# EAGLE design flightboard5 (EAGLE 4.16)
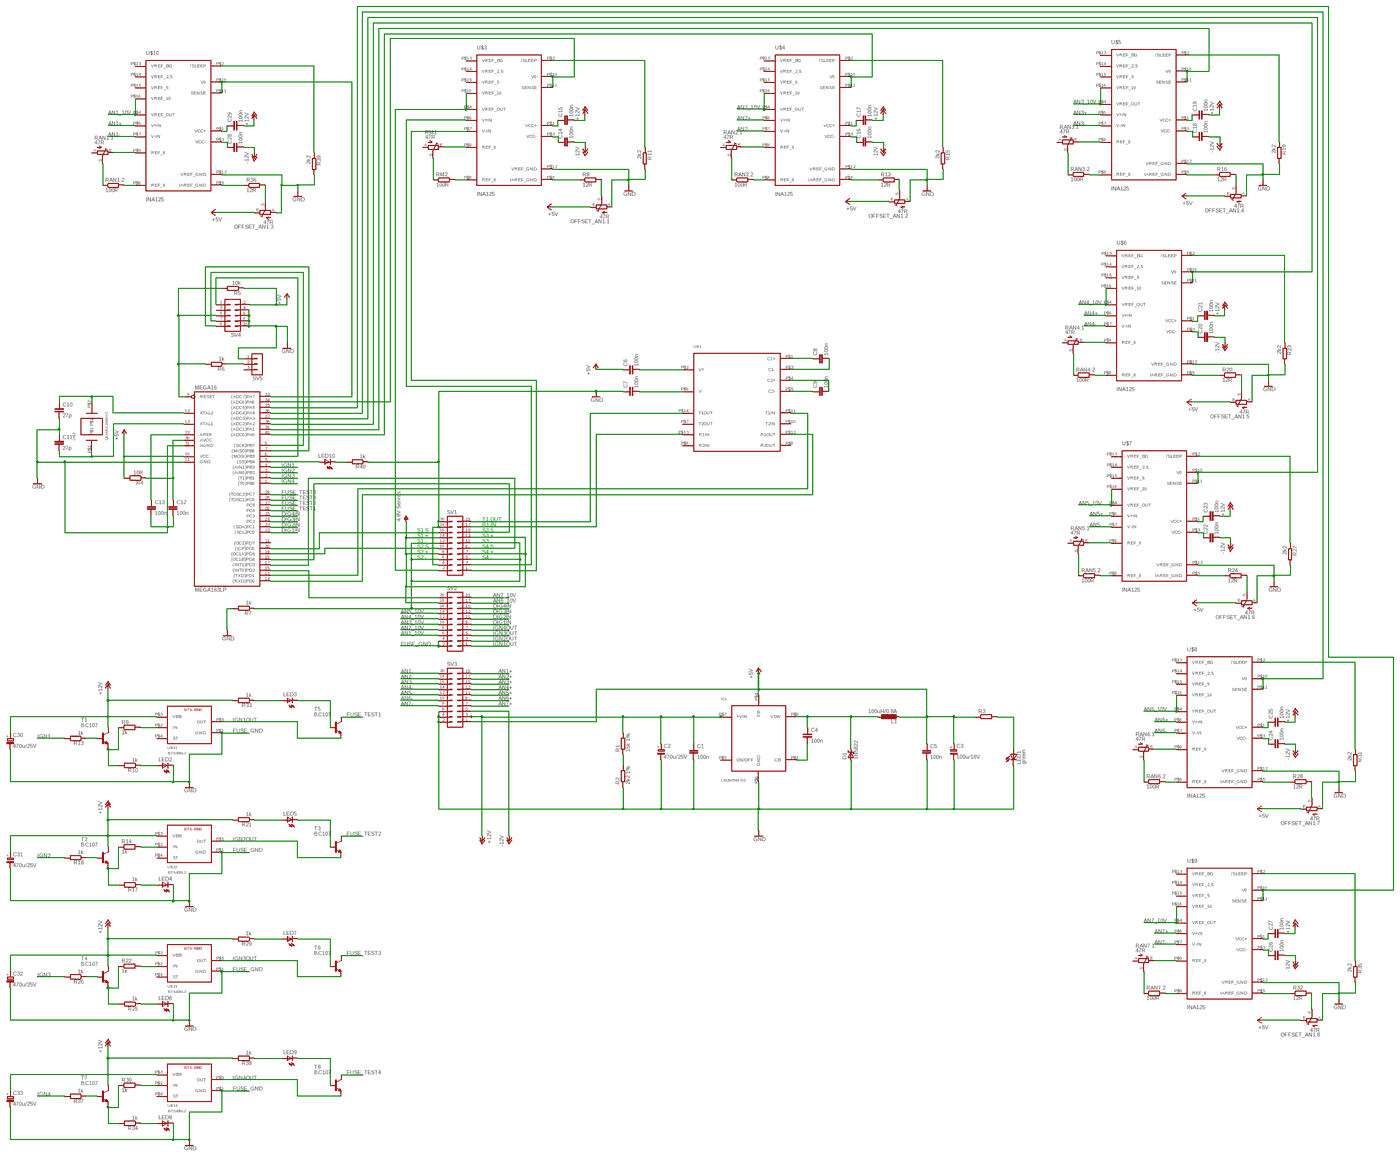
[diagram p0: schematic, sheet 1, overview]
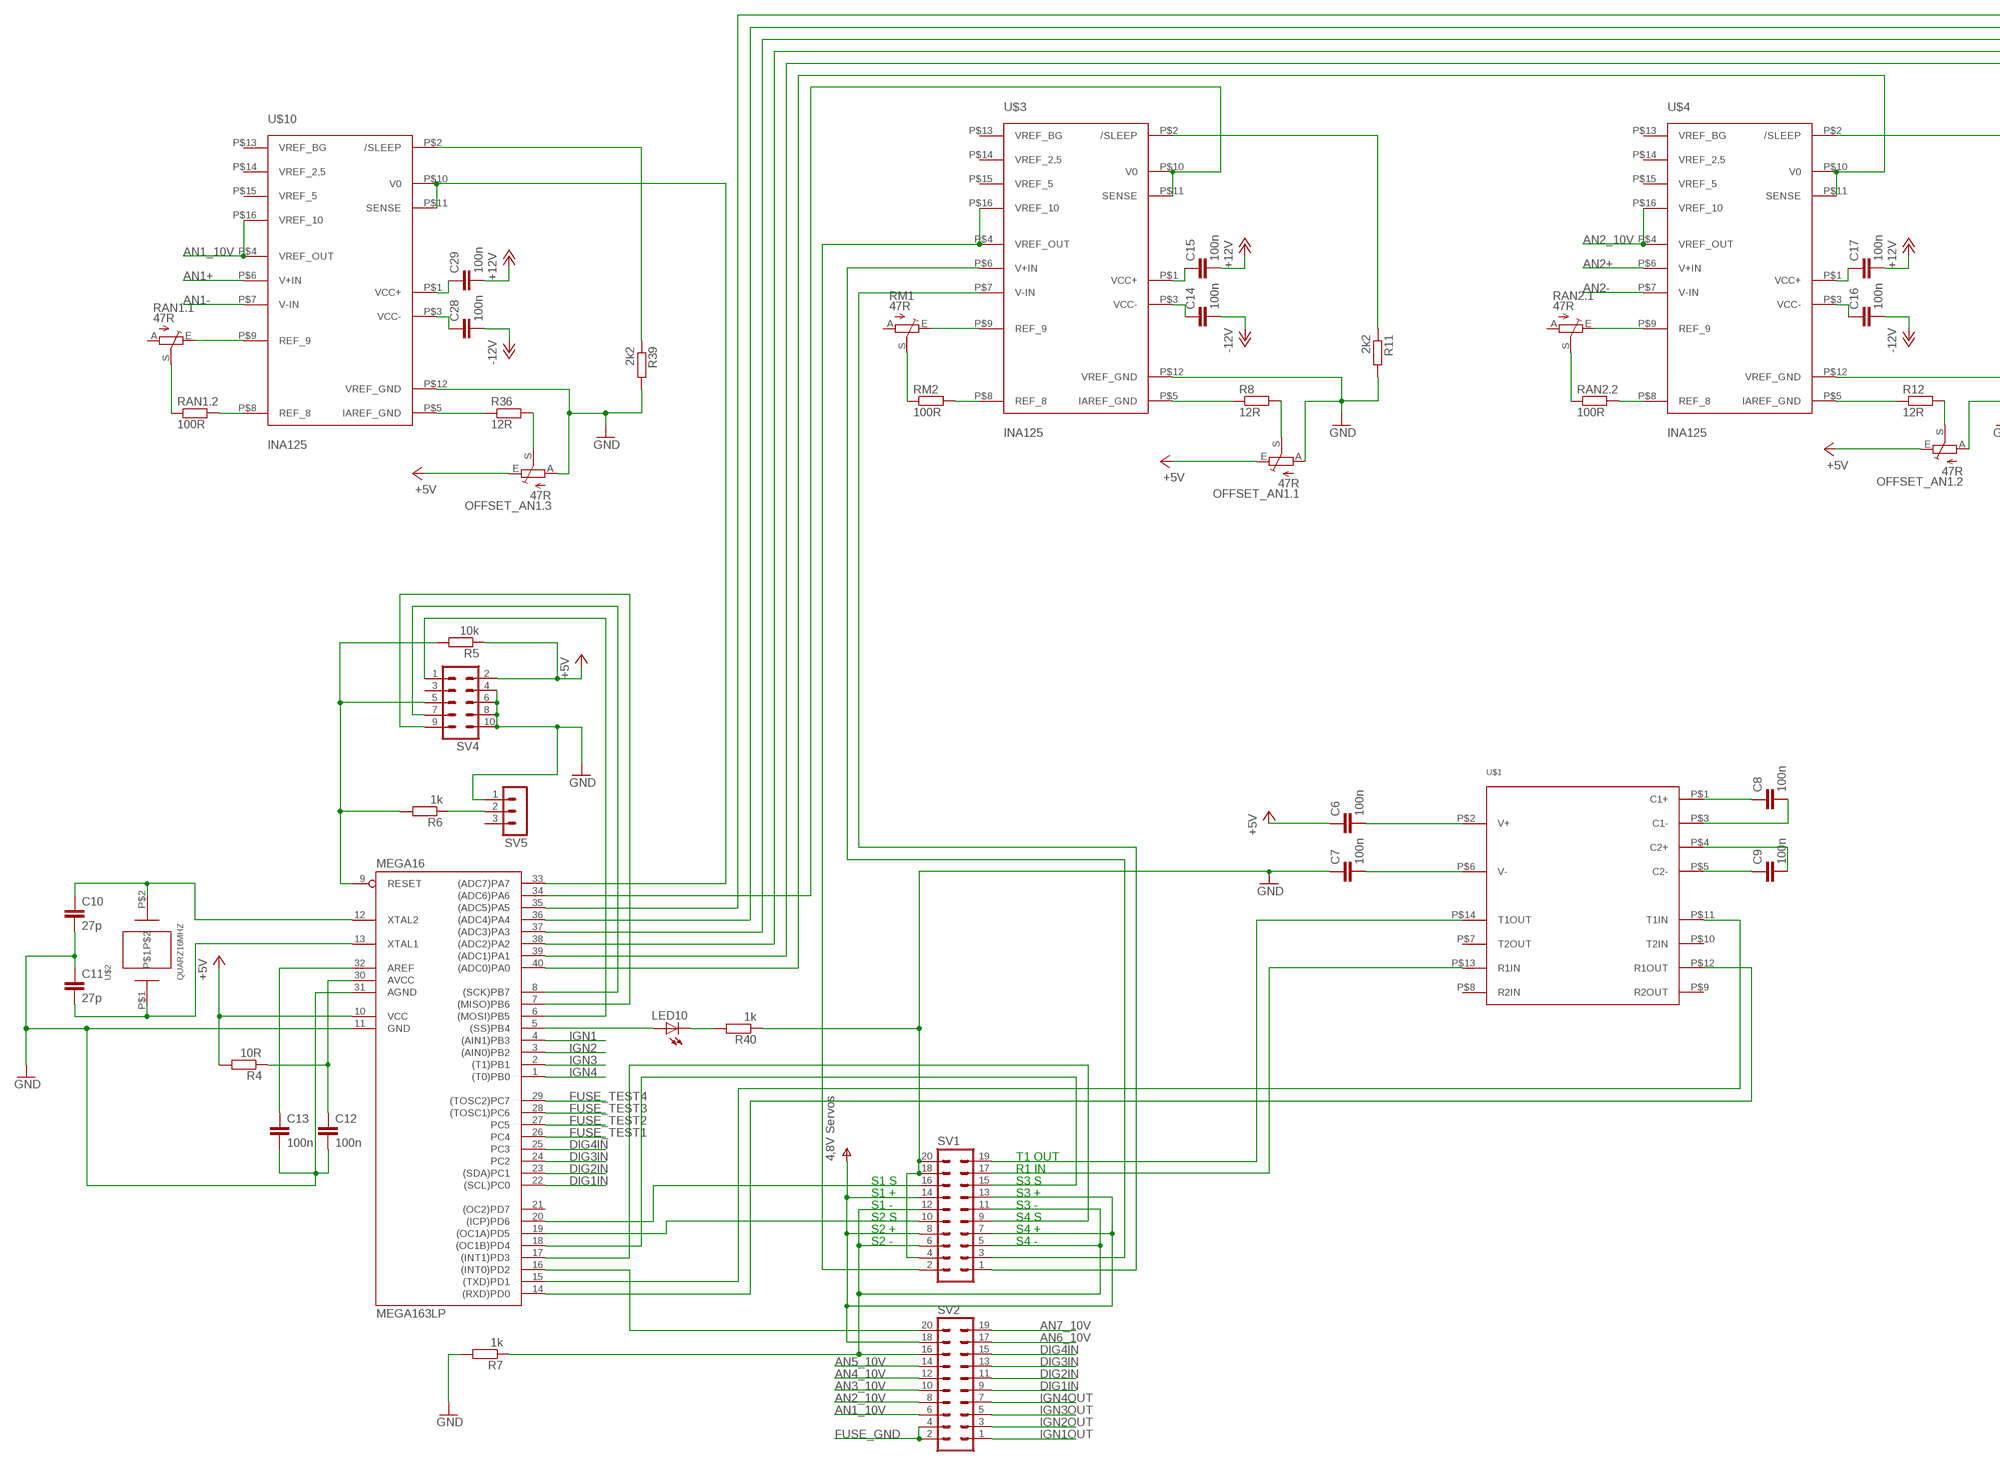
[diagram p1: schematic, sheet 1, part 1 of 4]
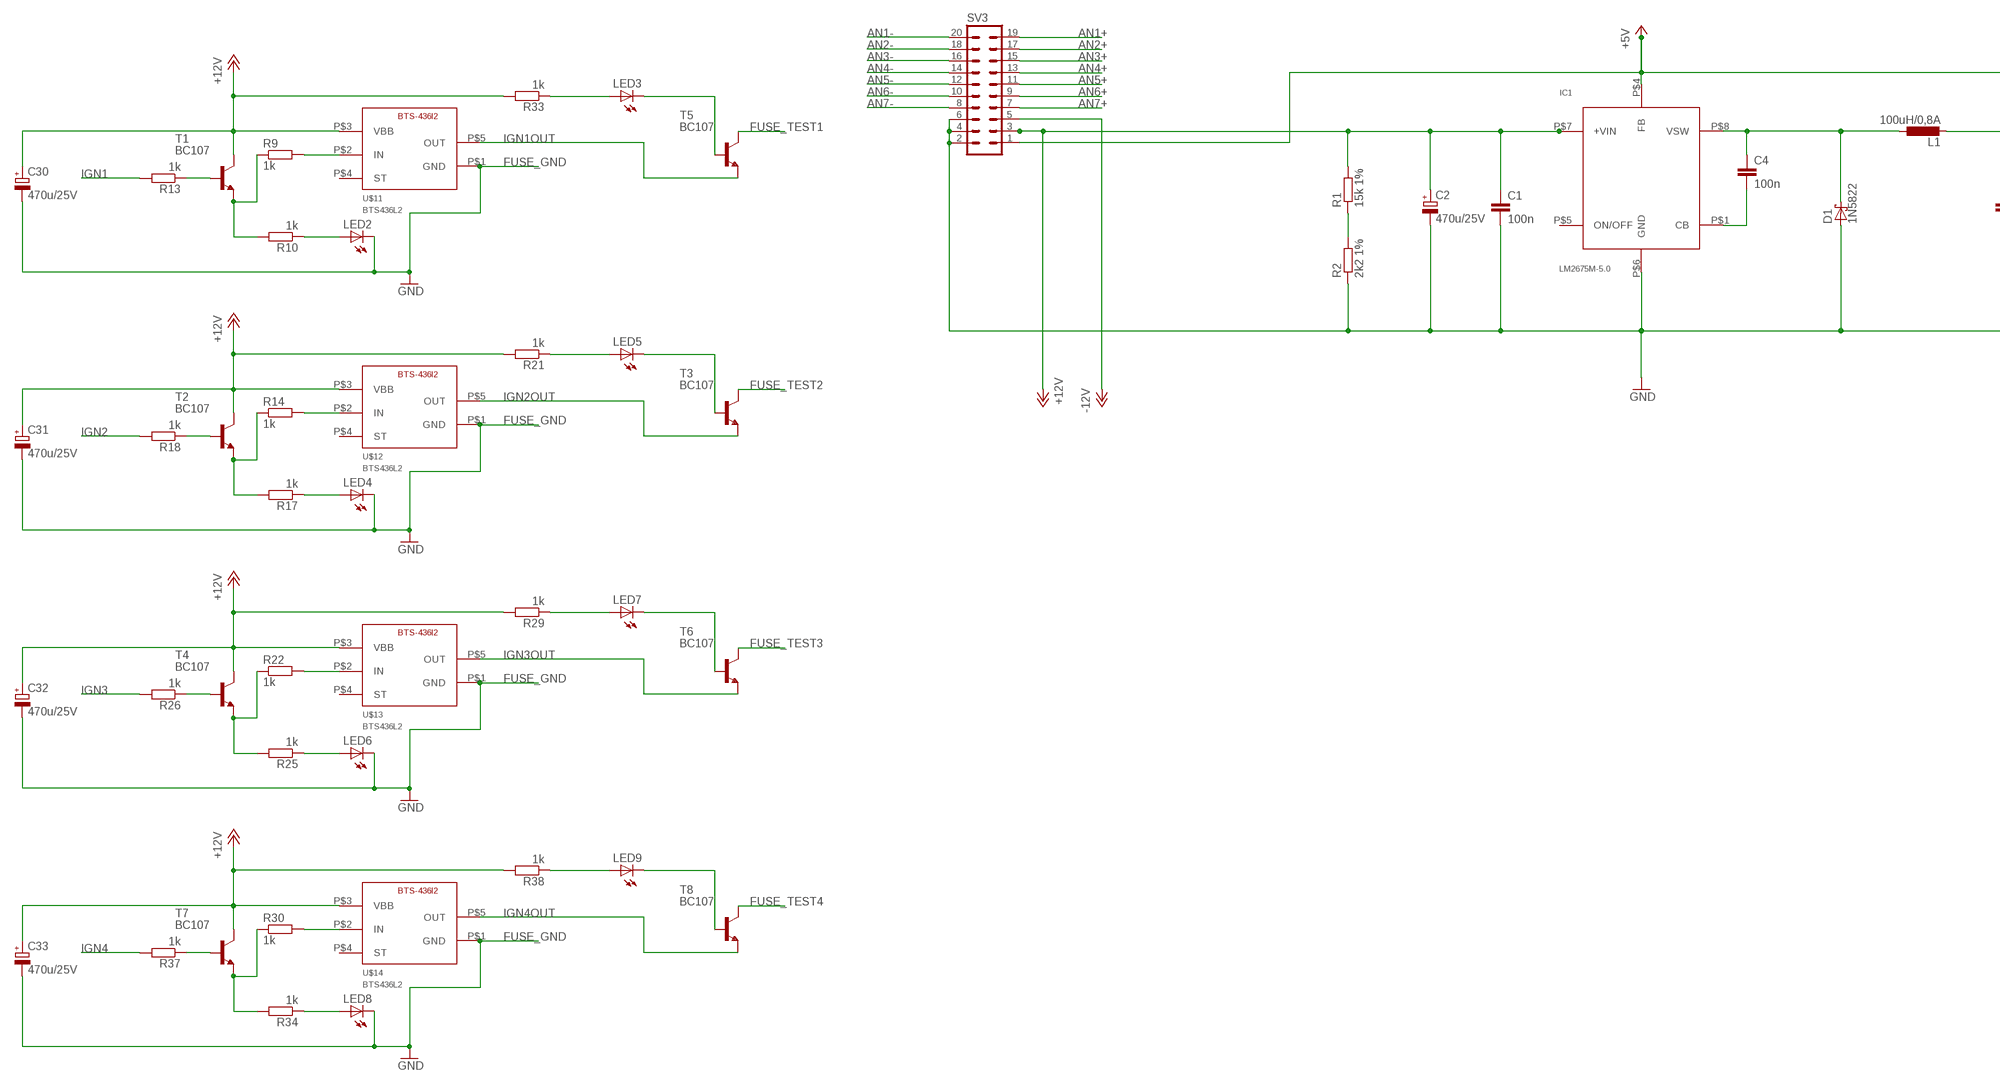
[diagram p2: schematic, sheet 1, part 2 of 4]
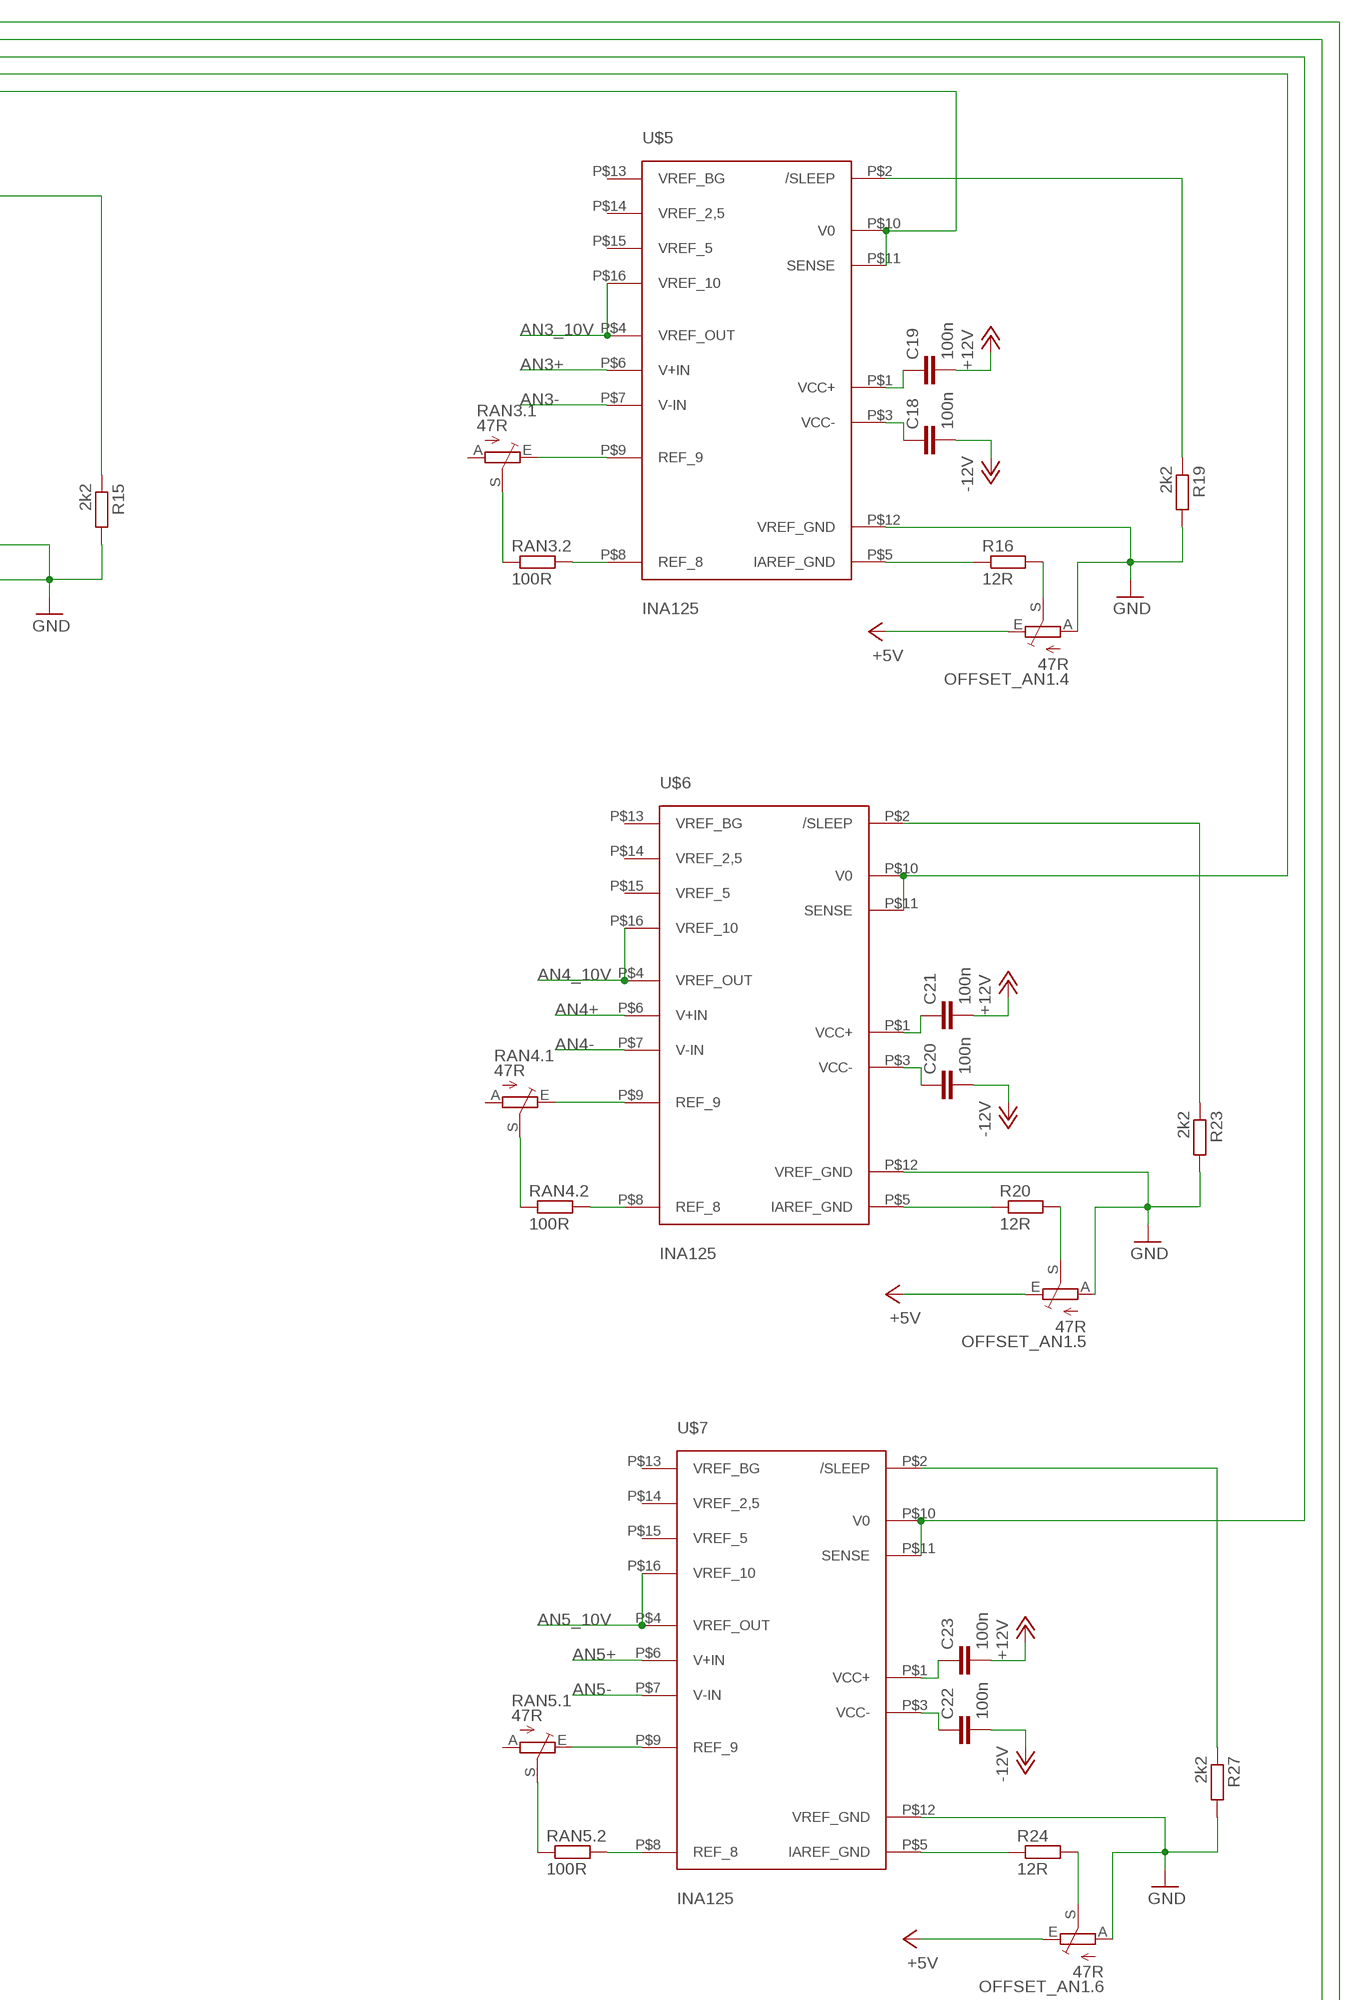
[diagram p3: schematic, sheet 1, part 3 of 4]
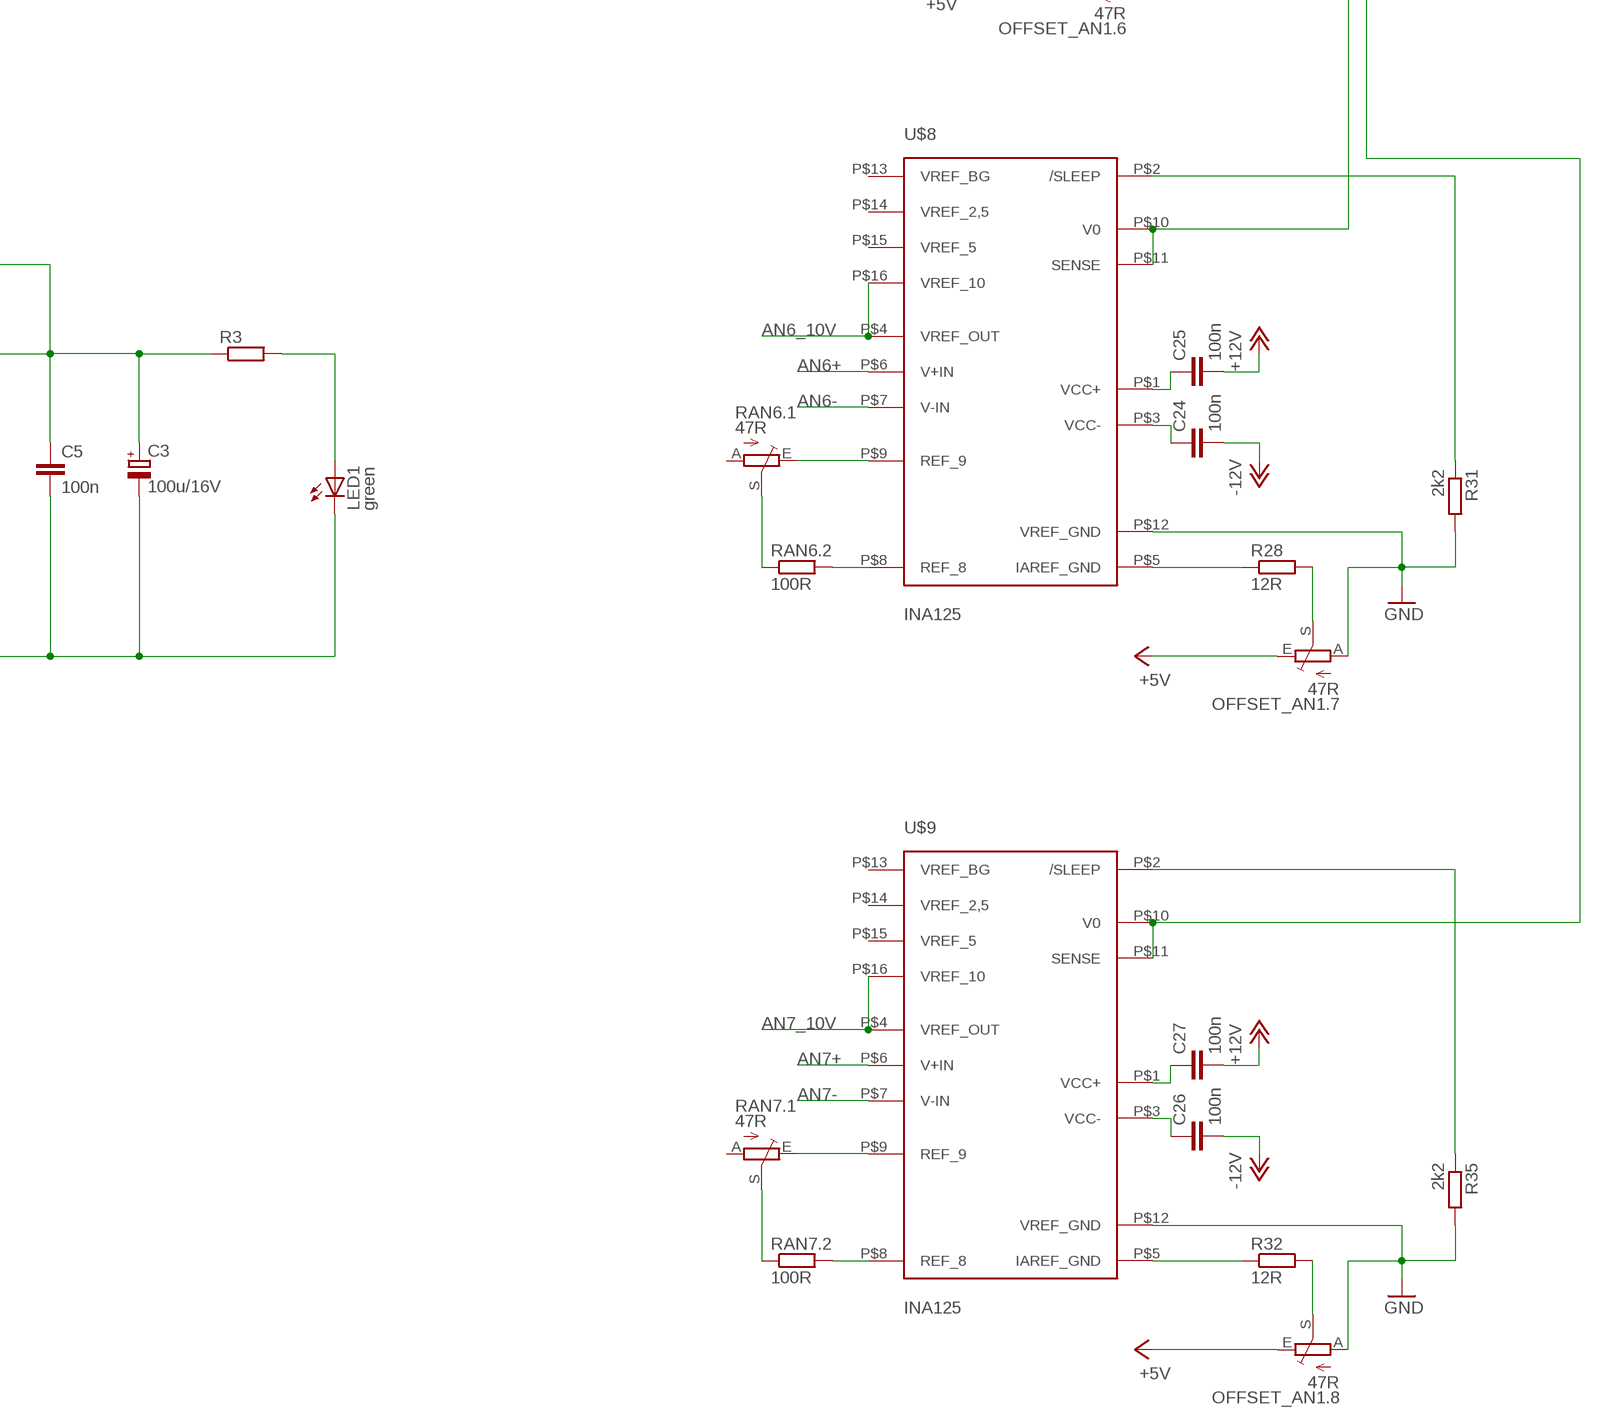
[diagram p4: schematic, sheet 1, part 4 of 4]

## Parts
C1  100n  C-EU025-024X044  [C025-024X044]
C2  470u/25V  CPOL-EUE3.5-10  [E3,5-10]
C3  100u/16V  CPOL-EUE2.5-5  [E2,5-5]
C4  100n  C-EU025-024X044  [C025-024X044]
C5  100n  C-EU025-024X044  [C025-024X044]
C6  100n  C-EU025-024X044  [C025-024X044]
C7  100n  C-EU025-024X044  [C025-024X044]
C8  100n  C-EU025-024X044  [C025-024X044]
C9  100n  C-EU025-024X044  [C025-024X044]
C10  27p  C-EU025-024X044  [C025-024X044]
C11  27p  C-EU025-024X044  [C025-024X044]
C12  100n  C-EU025-024X044  [C025-024X044]
C13  100n  C-EU025-024X044  [C025-024X044]
C14  100n  C-EU025-024X044  [C025-024X044]
C15  100n  C-EU025-024X044  [C025-024X044]
C16  100n  C-EU025-024X044  [C025-024X044]
C17  100n  C-EU025-024X044  [C025-024X044]
C18  100n  C-EU025-024X044  [C025-024X044]
C19  100n  C-EU025-024X044  [C025-024X044]
C20  100n  C-EU025-024X044  [C025-024X044]
C21  100n  C-EU025-024X044  [C025-024X044]
C22  100n  C-EU025-024X044  [C025-024X044]
C23  100n  C-EU025-024X044  [C025-024X044]
C24  100n  C-EU025-024X044  [C025-024X044]
C25  100n  C-EU025-024X044  [C025-024X044]
C26  100n  C-EU025-024X044  [C025-024X044]
C27  100n  C-EU025-024X044  [C025-024X044]
C28  100n  C-EU025-024X044  [C025-024X044]
C29  100n  C-EU025-024X044  [C025-024X044]
C30  470u/25V  CPOL-EUE3.5-10  [E3,5-10]
C31  470u/25V  CPOL-EUE3.5-10  [E3,5-10]
C32  470u/25V  CPOL-EUE3.5-10  [E3,5-10]
C33  470u/25V  CPOL-EUE3.5-10  [E3,5-10]
D1  1N5822  1N5908  [C4111-15]
IC1  LM2675M-5.0  [DIL-8]
L1  100uH/0,8A  L-EU0207/5V  [0207/5V]
LED1  green  LED3MM  [LED3MM]
LED2  LED3MM  [LED3MM]
LED3  LED3MM  [LED3MM]
LED4  LED3MM  [LED3MM]
LED5  LED3MM  [LED3MM]
LED6  LED3MM  [LED3MM]
LED7  LED3MM  [LED3MM]
LED8  LED3MM  [LED3MM]
LED9  LED3MM  [LED3MM]
LED10  LED3MM  [LED3MM]
MEGA16  MEGA163LP  [DIL40]
OFFSET_AN1.1  47R  TRIM_EU-B90P  [SP19L]
OFFSET_AN1.2  47R  TRIM_EU-B90P  [SP19L]
OFFSET_AN1.3  47R  TRIM_EU-B90P  [SP19L]
OFFSET_AN1.4  47R  TRIM_EU-B90P  [SP19L]
OFFSET_AN1.5  47R  TRIM_EU-B90P  [SP19L]
OFFSET_AN1.6  47R  TRIM_EU-B90P  [SP19L]
OFFSET_AN1.7  47R  TRIM_EU-B90P  [SP19L]
OFFSET_AN1.8  47R  TRIM_EU-B90P  [SP19L]
R1  15k 1%  R-EU_0207/10  [0207/10]
R2  2k2 1%  R-EU_0207/10  [0207/10]
R3  R-EU_0207/10  [0207/10]
R4  10R  R-EU_0309/10  [0309/10]
R5  10k  R-EU_0207/10  [0207/10]
R6  1k  R-EU_0207/10  [0207/10]
R7  1k  R-EU_0207/10  [0207/10]
R8  12R  R-EU_0309/10  [0309/10]
R9  1k  R-EU_0207/10  [0207/10]
R10  1k  R-EU_0207/10  [0207/10]
R11  2k2  R-EU_0309/10  [0309/10]
R12  12R  R-EU_0309/10  [0309/10]
R13  1k  R-EU_0207/10  [0207/10]
R14  1k  R-EU_0207/10  [0207/10]
R15  2k2  R-EU_0309/10  [0309/10]
R16  12R  R-EU_0309/10  [0309/10]
R17  1k  R-EU_0207/10  [0207/10]
R18  1k  R-EU_0207/10  [0207/10]
R19  2k2  R-EU_0309/10  [0309/10]
R20  12R  R-EU_0309/10  [0309/10]
R21  1k  R-EU_0207/10  [0207/10]
R22  1k  R-EU_0207/10  [0207/10]
R23  2k2  R-EU_0309/10  [0309/10]
R24  12R  R-EU_0309/10  [0309/10]
R25  1k  R-EU_0207/10  [0207/10]
R26  1k  R-EU_0207/10  [0207/10]
R27  2k2  R-EU_0309/10  [0309/10]
R28  12R  R-EU_0309/10  [0309/10]
R29  1k  R-EU_0207/10  [0207/10]
R30  1k  R-EU_0207/10  [0207/10]
R31  2k2  R-EU_0309/10  [0309/10]
R32  12R  R-EU_0309/10  [0309/10]
R33  1k  R-EU_0207/10  [0207/10]
R34  1k  R-EU_0207/10  [0207/10]
R35  2k2  R-EU_0309/10  [0309/10]
R36  12R  R-EU_0309/10  [0309/10]
R37  1k  R-EU_0207/10  [0207/10]
R38  1k  R-EU_0207/10  [0207/10]
R39  2k2  R-EU_0309/10  [0309/10]
R40  1k  R-EU_0309/10  [0309/10]
RAN1.1  47R  TRIM_EU-B90P  [SP19L]
RAN1.2  100R  R-EU_0309/10  [0309/10]
RAN2.1  47R  TRIM_EU-B90P  [SP19L]
RAN2.2  100R  R-EU_0309/10  [0309/10]
RAN3.1  47R  TRIM_EU-B90P  [SP19L]
RAN3.2  100R  R-EU_0309/10  [0309/10]
RAN4.1  47R  TRIM_EU-B90P  [SP19L]
RAN4.2  100R  R-EU_0309/10  [0309/10]
RAN5.1  47R  TRIM_EU-B90P  [SP19L]
RAN5.2  100R  R-EU_0309/10  [0309/10]
RAN6.1  47R  TRIM_EU-B90P  [SP19L]
RAN6.2  100R  R-EU_0309/10  [0309/10]
RAN7.1  47R  TRIM_EU-B90P  [SP19L]
RAN7.2  100R  R-EU_0309/10  [0309/10]
RM1  47R  TRIM_EU-B90P  [SP19L]
RM2  100R  R-EU_0309/10  [0309/10]
SV1  MA10-2W  [MA10-2W]
SV2  MA10-2W  [MA10-2W]
SV3  MA10-2W  [MA10-2W]
SV4  MA05-2  [MA05-2]
SV5  MA03-1  [MA03-1]
T1  BC107  [TO18]
T2  BC107  [TO18]
T3  BC107  [TO18]
T4  BC107  [TO18]
T5  BC107  [TO18]
T6  BC107  [TO18]
T7  BC107  [TO18]
T8  BC107  [TO18]
U$1  MAX232  [DIL-16]
U$2  QUARZ16MHZ  [QUARZ16MHZ]
U$3  INA125  [DIL-16]
U$4  INA125  [DIL-16]
U$5  INA125  [DIL-16]
U$6  INA125  [DIL-16]
U$7  INA125  [DIL-16]
U$8  INA125  [DIL-16]
U$9  INA125  [DIL-16]
U$10  INA125  [DIL-16]
U$11  BTS436L2  [TO-GEHÄUSE]
U$12  BTS436L2  [TO-GEHÄUSE]
U$13  BTS436L2  [TO-GEHÄUSE]
U$14  BTS436L2  [TO-GEHÄUSE]

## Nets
+5V: C3.+ C5.1 C6.1 IC1.P$4(FB) L1.2 MEGA16.10(VCC) OFFSET_AN1.1.E OFFSET_AN1.2.E OFFSET_AN1.3.E OFFSET_AN1.4.E OFFSET_AN1.5.E OFFSET_AN1.6.E OFFSET_AN1.7.E OFFSET_AN1.8.E R3.1 R4.2 R5.1 SV3.1 SV4.2
+12V: C1.1 C2.+ C15.2 C17.2 C19.2 C21.2 C23.2 C25.2 C27.2 C29.2 C30.+ C31.+ C32.+ C33.+ IC1.P$7(+VIN) R1.2 R21.2 R29.2 R33.2 R38.2 SV3.3 T1.3(C) T2.3(C) T4.3(C) T7.3(C) U$11.P$3(VBB) U$12.P$3(VBB) U$13.P$3(VBB) U$14.P$3(VBB)
-12V: C14.2 C16.2 C18.2 C20.2 C22.2 C24.2 C26.2 C28.2 SV3.5
AN1+: SV3.19 U$10.P$6(V+IN)
AN1-: SV3.20 U$10.P$7(V-IN)
AN1_10V: SV2.6 U$10.P$4(VREF_OUT) U$10.P$16(VREF_10)
AN2+: SV3.17 U$4.P$6(V+IN)
AN2-: SV3.18 U$4.P$7(V-IN)
AN2_10V: SV2.8 U$4.P$4(VREF_OUT) U$4.P$16(VREF_10)
AN3+: SV3.15 U$5.P$6(V+IN)
AN3-: SV3.16 U$5.P$7(V-IN)
AN3_10V: SV2.10 U$5.P$4(VREF_OUT) U$5.P$16(VREF_10)
AN4+: SV3.13 U$6.P$6(V+IN)
AN4-: SV3.14 U$6.P$7(V-IN)
AN4_10V: SV2.12 U$6.P$4(VREF_OUT) U$6.P$16(VREF_10)
AN5+: SV3.11 U$7.P$6(V+IN)
AN5-: SV3.12 U$7.P$7(V-IN)
AN5_10V: SV2.14 U$7.P$4(VREF_OUT) U$7.P$16(VREF_10)
AN6+: SV3.9 U$8.P$6(V+IN)
AN6-: SV3.10 U$8.P$7(V-IN)
AN6_10V: SV2.17 U$8.P$4(VREF_OUT) U$8.P$16(VREF_10)
AN7+: SV3.7 U$9.P$6(V+IN)
AN7-: SV3.8 U$9.P$7(V-IN)
AN7_10V: SV2.19 U$9.P$4(VREF_OUT) U$9.P$16(VREF_10)
DIG1IN: MEGA16.22((SCL)PC0) SV2.9
DIG2IN: MEGA16.23((SDA)PC1) SV2.11
DIG3IN: MEGA16.24(PC2) SV2.13
DIG4IN: MEGA16.25(PC3) SV2.15
FUSE_GND: C1.2 C2.- C3.- C5.2 C7.1 C10.2 C11.1 C12.2 C13.2 C30.- C31.- C32.- C33.- D1.A IC1.P$6(GND) LED1.K(C) LED2.K(C) LED4.K(C) LED6.K(C) LED8.K(C) MEGA16.11(GND) MEGA16.31(AGND) OFFSET_AN1.1.A OFFSET_AN1.2.A OFFSET_AN1.3.A OFFSET_AN1.4.A OFFSET_AN1.5.A OFFSET_AN1.6.A OFFSET_AN1.7.A OFFSET_AN1.8.A R2.1 R7.2 R11.2 R15.2 R19.2 R23.2 R27.2 R31.2 R35.2 R39.2 R40.1 SV1.4 SV1.18 SV1.20 SV2.2 SV2.4 SV3.2 SV3.4 SV3.6 SV4.4 SV4.6 SV4.8 SV4.10 SV5.1 U$3.P$12(VREF_GND) U$4.P$12(VREF_GND) U$5.P$12(VREF_GND) U$6.P$12(VREF_GND) U$7.P$12(VREF_GND) U$8.P$12(VREF_GND) U$9.P$12(VREF_GND) U$10.P$12(VREF_GND) U$11.P$1(GND) U$12.P$1(GND) U$13.P$1(GND) U$14.P$1(GND) ; supply symbol labelled GND
FUSE_TEST1: MEGA16.26(PC4) T5.3(C)
FUSE_TEST2: MEGA16.27(PC5) T3.3(C)
FUSE_TEST3: MEGA16.28((TOSC1)PC6) T6.3(C)
FUSE_TEST4: MEGA16.29((TOSC2)PC7) T8.3(C)
IGN1: MEGA16.4((AIN1)PB3) R13.2
IGN1OUT: SV2.1 T5.1(E) U$11.P$5(OUT)
IGN2: MEGA16.3((AIN0)PB2) R18.2
IGN2OUT: SV2.3 T3.1(E) U$12.P$5(OUT)
IGN3: MEGA16.2((T1)PB1) R26.2
IGN3OUT: SV2.5 T6.1(E) U$13.P$5(OUT)
IGN4: MEGA16.1((T0)PB0) R37.2
IGN4OUT: SV2.7 T8.1(E) U$14.P$5(OUT)
N$1: R1.1 R2.2
N$2: C4.2 IC1.P$1(CB)
N$3: C4.1 D1.C IC1.P$8(VSW) L1.1
N$4: C6.2 U$1.P$2(V+)
N$5: LED1.A R3.2
N$6: C7.2 U$1.P$6(V-)
N$7: C9.1 U$1.P$5(C2-)
N$8: C8.1 U$1.P$1(C1+)
N$9: C8.2 U$1.P$3(C1-)
N$10: C9.2 U$1.P$4(C2+)
N$11: SV1.17 U$1.P$13(R1IN)
N$12: SV1.19 U$1.P$14(T1OUT)
N$13: MEGA16.14((RXD)PD0) U$1.P$12(R1OUT)
N$14: MEGA16.15((TXD)PD1) U$1.P$11(T1IN)
N$15: C11.2 MEGA16.13(XTAL1) U$2.P$1
N$16: C10.1 MEGA16.12(XTAL2) U$2.P$2
N$17: MEGA16.17((INT1)PD3) SV1.9
N$18: C12.1 MEGA16.30(AVCC) R4.1
N$19: C13.1 MEGA16.32(AREF)
N$20: MEGA16.9(RESET) R5.2 R6.2 SV4.5
N$21: MEGA16.16((INT0)PD2) SV2.20
N$22: R6.1 SV5.2
N$23: MEGA16.20((ICP)PD6) SV1.16
N$24: MEGA16.19((OC1A)PD5) SV1.10
N$25: R7.1 SV1.5 SV1.6 SV1.11 SV1.12 SV2.16
N$26: MEGA16.18((OC1B)PD4) SV1.15
N$27: C14.1 U$3.P$3(VCC-)
N$28: C15.1 U$3.P$1(VCC+)
N$29: MEGA16.34((ADC6)PA6) U$3.P$10(V0) U$3.P$11(SENSE)
N$30: RM2.2 U$3.P$8(REF_8)
N$31: RM1.E U$3.P$9(REF_9)
N$32: RM1.S RM2.1
N$33: SV1.2 U$3.P$4(VREF_OUT) U$3.P$16(VREF_10)
N$34: R11.1 U$3.P$2(/SLEEP)
N$35: C16.1 U$4.P$3(VCC-)
N$36: SV1.3 U$3.P$6(V+IN)
N$37: SV1.1 U$3.P$7(V-IN)
N$38: C17.1 U$4.P$1(VCC+)
N$39: MEGA16.40((ADC0)PA0) U$4.P$10(V0) U$4.P$11(SENSE)
N$40: RAN2.2.2 U$4.P$8(REF_8)
N$41: RAN2.1.E U$4.P$9(REF_9)
N$42: RAN2.1.S RAN2.2.1
N$43: R15.1 U$4.P$2(/SLEEP)
N$44: OFFSET_AN1.3.S R36.2
N$45: R9.2 U$11.P$2(IN)
N$46: OFFSET_AN1.1.S R8.2
N$47: C18.1 U$5.P$3(VCC-)
N$48: C19.1 U$5.P$1(VCC+)
N$49: C26.1 U$9.P$3(VCC-)
N$50: RAN3.2.2 U$5.P$8(REF_8)
N$51: RAN3.1.E U$5.P$9(REF_9)
N$52: RAN3.1.S RAN3.2.1
N$53: R19.1 U$5.P$2(/SLEEP)
N$54: OFFSET_AN1.2.S R12.2
N$55: OFFSET_AN1.4.S R16.2
N$56: OFFSET_AN1.5.S R20.2
N$57: C20.1 U$6.P$3(VCC-)
N$58: C21.1 U$6.P$1(VCC+)
N$59: C27.1 U$9.P$1(VCC+)
N$60: RAN4.2.2 U$6.P$8(REF_8)
N$61: RAN4.1.E U$6.P$9(REF_9)
N$62: RAN4.1.S RAN4.2.1
N$63: R23.1 U$6.P$2(/SLEEP)
N$64: OFFSET_AN1.6.S R24.2
N$65: OFFSET_AN1.7.S R28.2
N$66: R14.2 U$12.P$2(IN)
N$67: C22.1 U$7.P$3(VCC-)
N$68: C23.1 U$7.P$1(VCC+)
N$69: C28.1 U$10.P$3(VCC-)
N$70: RAN5.2.2 U$7.P$8(REF_8)
N$71: RAN5.1.E U$7.P$9(REF_9)
N$72: RAN5.1.S RAN5.2.1
N$73: R27.1 U$7.P$2(/SLEEP)
N$74: R9.1 R10.2 T1.1(E)
N$75: R13.1 T1.2(B)
N$76: LED3.K(C) T5.2(B)
N$77: C24.1 U$8.P$3(VCC-)
N$78: C25.1 U$8.P$1(VCC+)
N$79: C29.1 U$10.P$1(VCC+)
N$80: RAN6.2.2 U$8.P$8(REF_8)
N$81: RAN6.1.E U$8.P$9(REF_9)
N$82: RAN6.1.S RAN6.2.1
N$83: R31.1 U$8.P$2(/SLEEP)
N$84: R14.1 R17.2 T2.1(E)
N$85: R18.1 T2.2(B)
N$86: LED4.A R17.1
N$87: RAN7.2.2 U$9.P$8(REF_8)
N$88: MEGA16.39((ADC1)PA1) U$5.P$10(V0) U$5.P$11(SENSE)
N$89: MEGA16.38((ADC2)PA2) U$6.P$10(V0) U$6.P$11(SENSE)
N$90: MEGA16.37((ADC3)PA3) U$7.P$10(V0) U$7.P$11(SENSE)
N$91: MEGA16.36((ADC4)PA4) U$8.P$10(V0) U$8.P$11(SENSE)
N$92: MEGA16.35((ADC5)PA5) U$9.P$10(V0) U$9.P$11(SENSE)
N$93: RAN7.1.E U$9.P$9(REF_9)
N$94: RAN7.1.S RAN7.2.1
N$95: R35.1 U$9.P$2(/SLEEP)
N$96: LED5.A R21.1
N$97: LED5.K(C) T3.2(B)
N$98: R22.2 U$13.P$2(IN)
N$99: MEGA16.33((ADC7)PA7) U$10.P$10(V0) U$10.P$11(SENSE)
N$100: RAN1.2.2 U$10.P$8(REF_8)
N$101: RAN1.1.E U$10.P$9(REF_9)
N$102: RAN1.1.S RAN1.2.1
N$103: R39.1 U$10.P$2(/SLEEP)
N$104: R22.1 R25.2 T4.1(E)
N$105: R26.1 T4.2(B)
N$106: LED6.A R25.1
N$107: MEGA16.8((SCK)PB7) SV4.7
N$108: MEGA16.6((MOSI)PB5) SV4.1
N$109: MEGA16.7((MISO)PB6) SV4.9
N$110: LED7.A R29.1
N$111: LED7.K(C) T6.2(B)
N$112: R36.1 U$10.P$5(IAREF_GND)
N$113: R8.1 U$3.P$5(IAREF_GND)
N$114: R12.1 U$4.P$5(IAREF_GND)
N$115: R16.1 U$5.P$5(IAREF_GND)
N$116: R20.1 U$6.P$5(IAREF_GND)
N$117: R24.1 U$7.P$5(IAREF_GND)
N$118: R28.1 U$8.P$5(IAREF_GND)
N$119: R32.1 U$9.P$5(IAREF_GND)
N$120: LED2.A R10.1
N$121: LED3.A R33.1
N$122: R30.2 U$14.P$2(IN)
N$123: R30.1 R34.2 T7.1(E)
N$124: R37.1 T7.2(B)
N$125: LED8.A R34.1
N$126: LED9.A R38.1
N$127: LED9.K(C) T8.2(B)
N$128: LED10.A MEGA16.5((SS)PB4)
N$129: LED10.K(C) R40.2
N$130: OFFSET_AN1.8.S R32.2
V+: SV1.7 SV1.8 SV1.13 SV1.14 SV2.18 ; supply symbol labelled 4,8V Servos
Unconnected: IC1.P$5(ON/OFF) MEGA16.21((OC2)PD7) RAN1.1.A RAN2.1.A RAN3.1.A RAN4.1.A RAN5.1.A RAN6.1.A RAN7.1.A RM1.A SV4.3 SV5.3 U$1.P$7(T2OUT) U$1.P$8(R2IN) U$1.P$9(R2OUT) U$1.P$10(T2IN) U$3.P$13(VREF_BG) U$3.P$14(VREF_2,5) U$3.P$15(VREF_5) U$4.P$13(VREF_BG) U$4.P$14(VREF_2,5) U$4.P$15(VREF_5) U$5.P$13(VREF_BG) U$5.P$14(VREF_2,5) U$5.P$15(VREF_5) U$6.P$13(VREF_BG) U$6.P$14(VREF_2,5) U$6.P$15(VREF_5) U$7.P$13(VREF_BG) U$7.P$14(VREF_2,5) U$7.P$15(VREF_5) U$8.P$13(VREF_BG) U$8.P$14(VREF_2,5) U$8.P$15(VREF_5) U$9.P$13(VREF_BG) U$9.P$14(VREF_2,5) U$9.P$15(VREF_5) U$10.P$13(VREF_BG) U$10.P$14(VREF_2,5) U$10.P$15(VREF_5) U$11.P$4(ST) U$12.P$4(ST) U$13.P$4(ST) U$14.P$4(ST)

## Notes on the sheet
- T1 OUT
- R1 IN
- S1 S | S3 S
- S1 + | S3 +
- S1 - | S3 -
- S2 S | S4 S
- S2 + | S4 +
- S2 - | S4 -

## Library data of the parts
C1 C4-C29 = rcl:C-EU: CAPACITOR, European symbol
C2 C3 C30-C33 = rcl:CPOL-EU: POLARIZED CAPACITOR, European symbol
D1 = diode:1N5908: DIODE
IC1 = eigene:LM2675M-5.0
L1 = rcl:L-EU: INDUCTOR, European symbol
LED1-LED10 = led:LED: LED
MEGA16 = atmel:MEGA163*P: MICROCONTROLLER 16 Kbytes FLASH, 1 Kbytes EEPROM 1 Kbytes SRAM UART 8-channel 10 bit ADC hardware multiplier
OFFSET_AN1.1-OFFSET_AN1.8 RAN1.1 RAN2.1 RAN3.1 RAN4.1 RAN5.1 RAN6.1 RAN7.1 RM1 = pot:TRIM_EU-: POTENTIOMETER
R1-R40 RAN1.2 RAN2.2 RAN3.2 RAN4.2 RAN5.2 RAN6.2 RAN7.2 RM2 = rcl:R-EU_: RESISTOR, European symbol
SV1-SV3 = con-lstb:MA10-2W: PIN HEADER
SV4 = con-lstb:MA05-2: PIN HEADER
SV5 = con-lstb:MA03-1: PIN HEADER
T1-T8 = transistor:BC107: NPN TRANSISTOR
U$1 = eigene:MAX232
U$2 = eigene:QUARZ16MHZ
U$3-U$10 = eigene:INA125
U$11-U$14 = eigene:BTS436L2

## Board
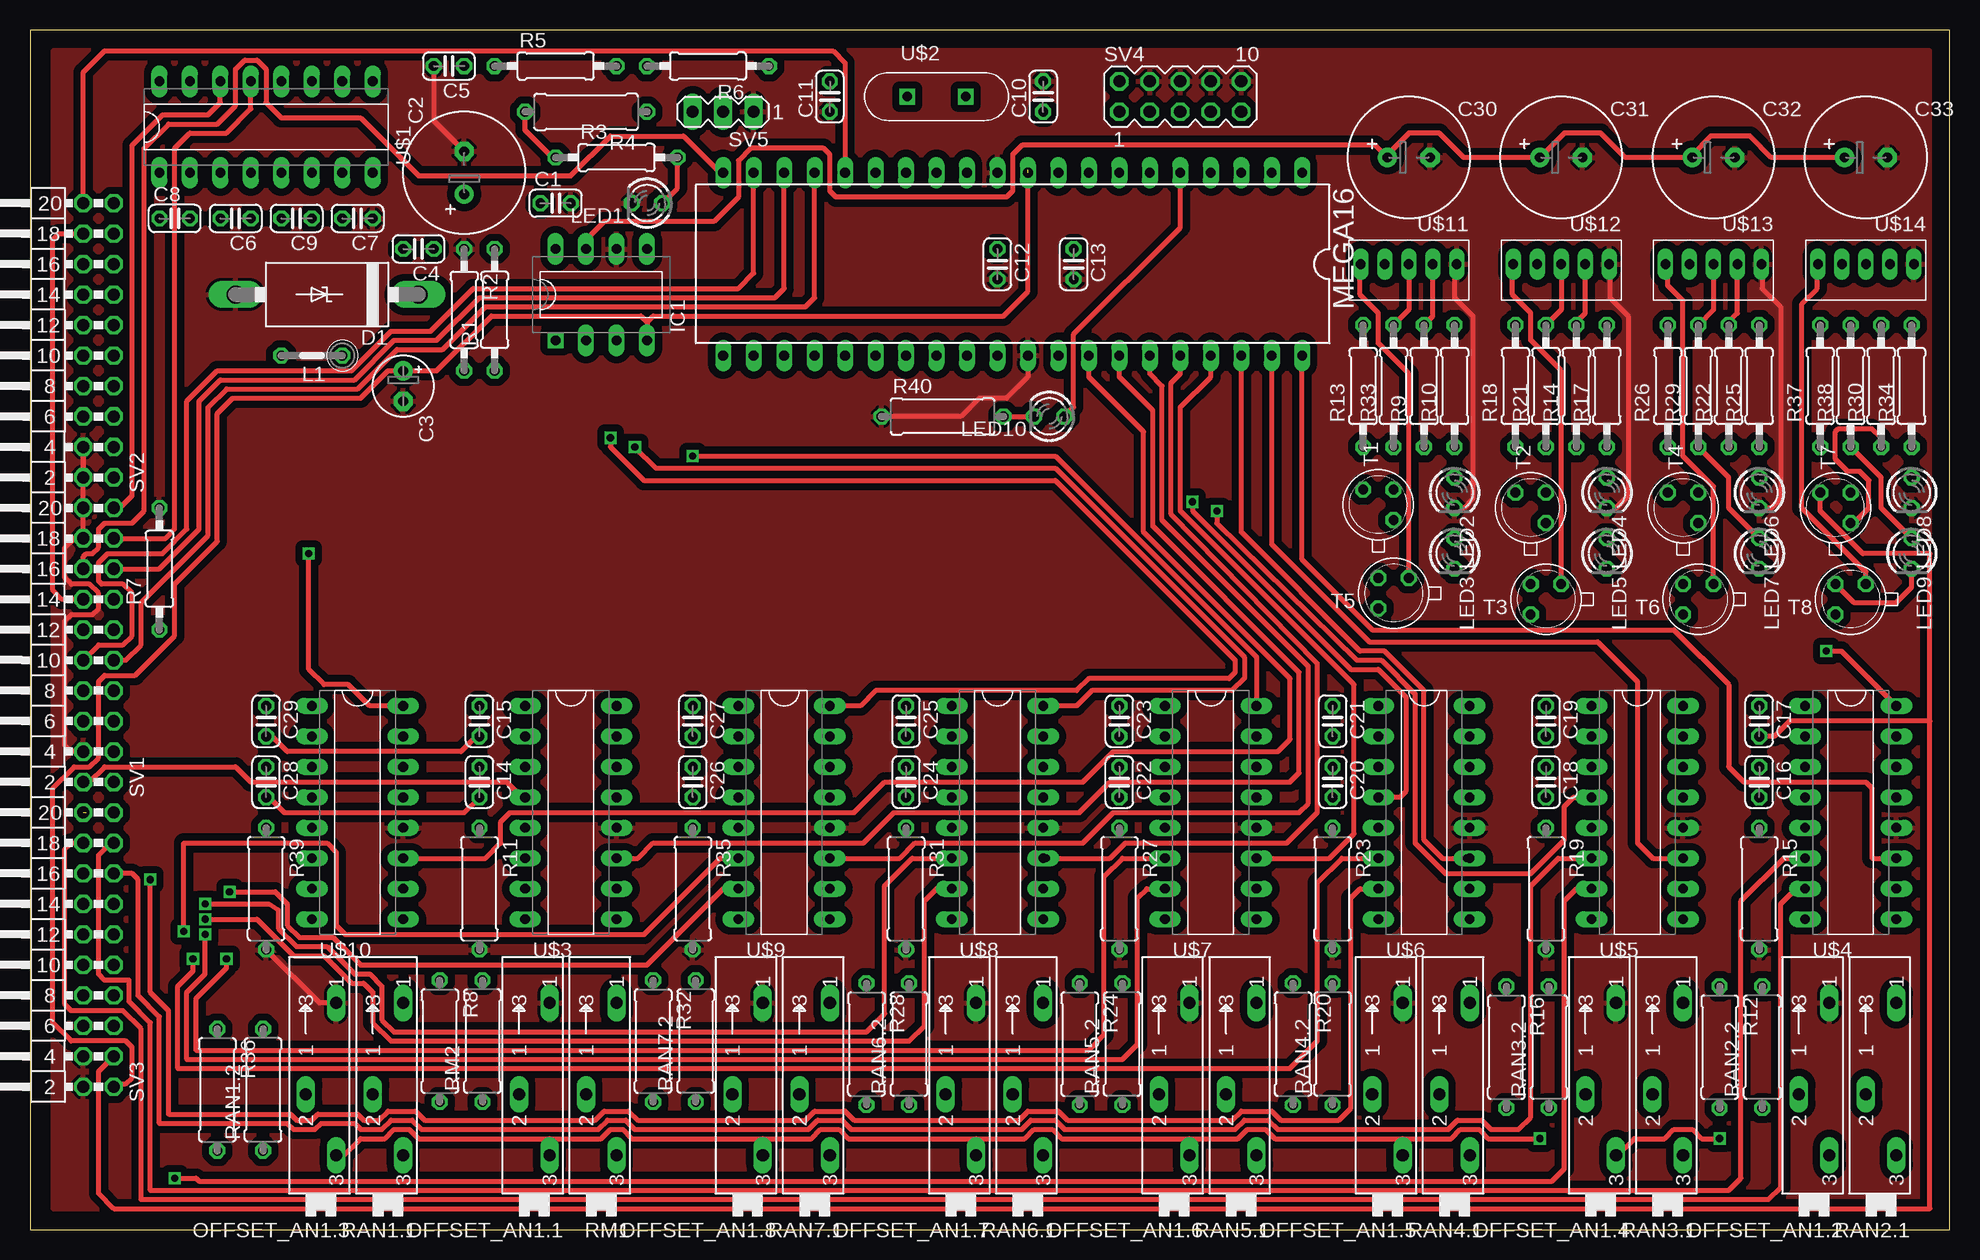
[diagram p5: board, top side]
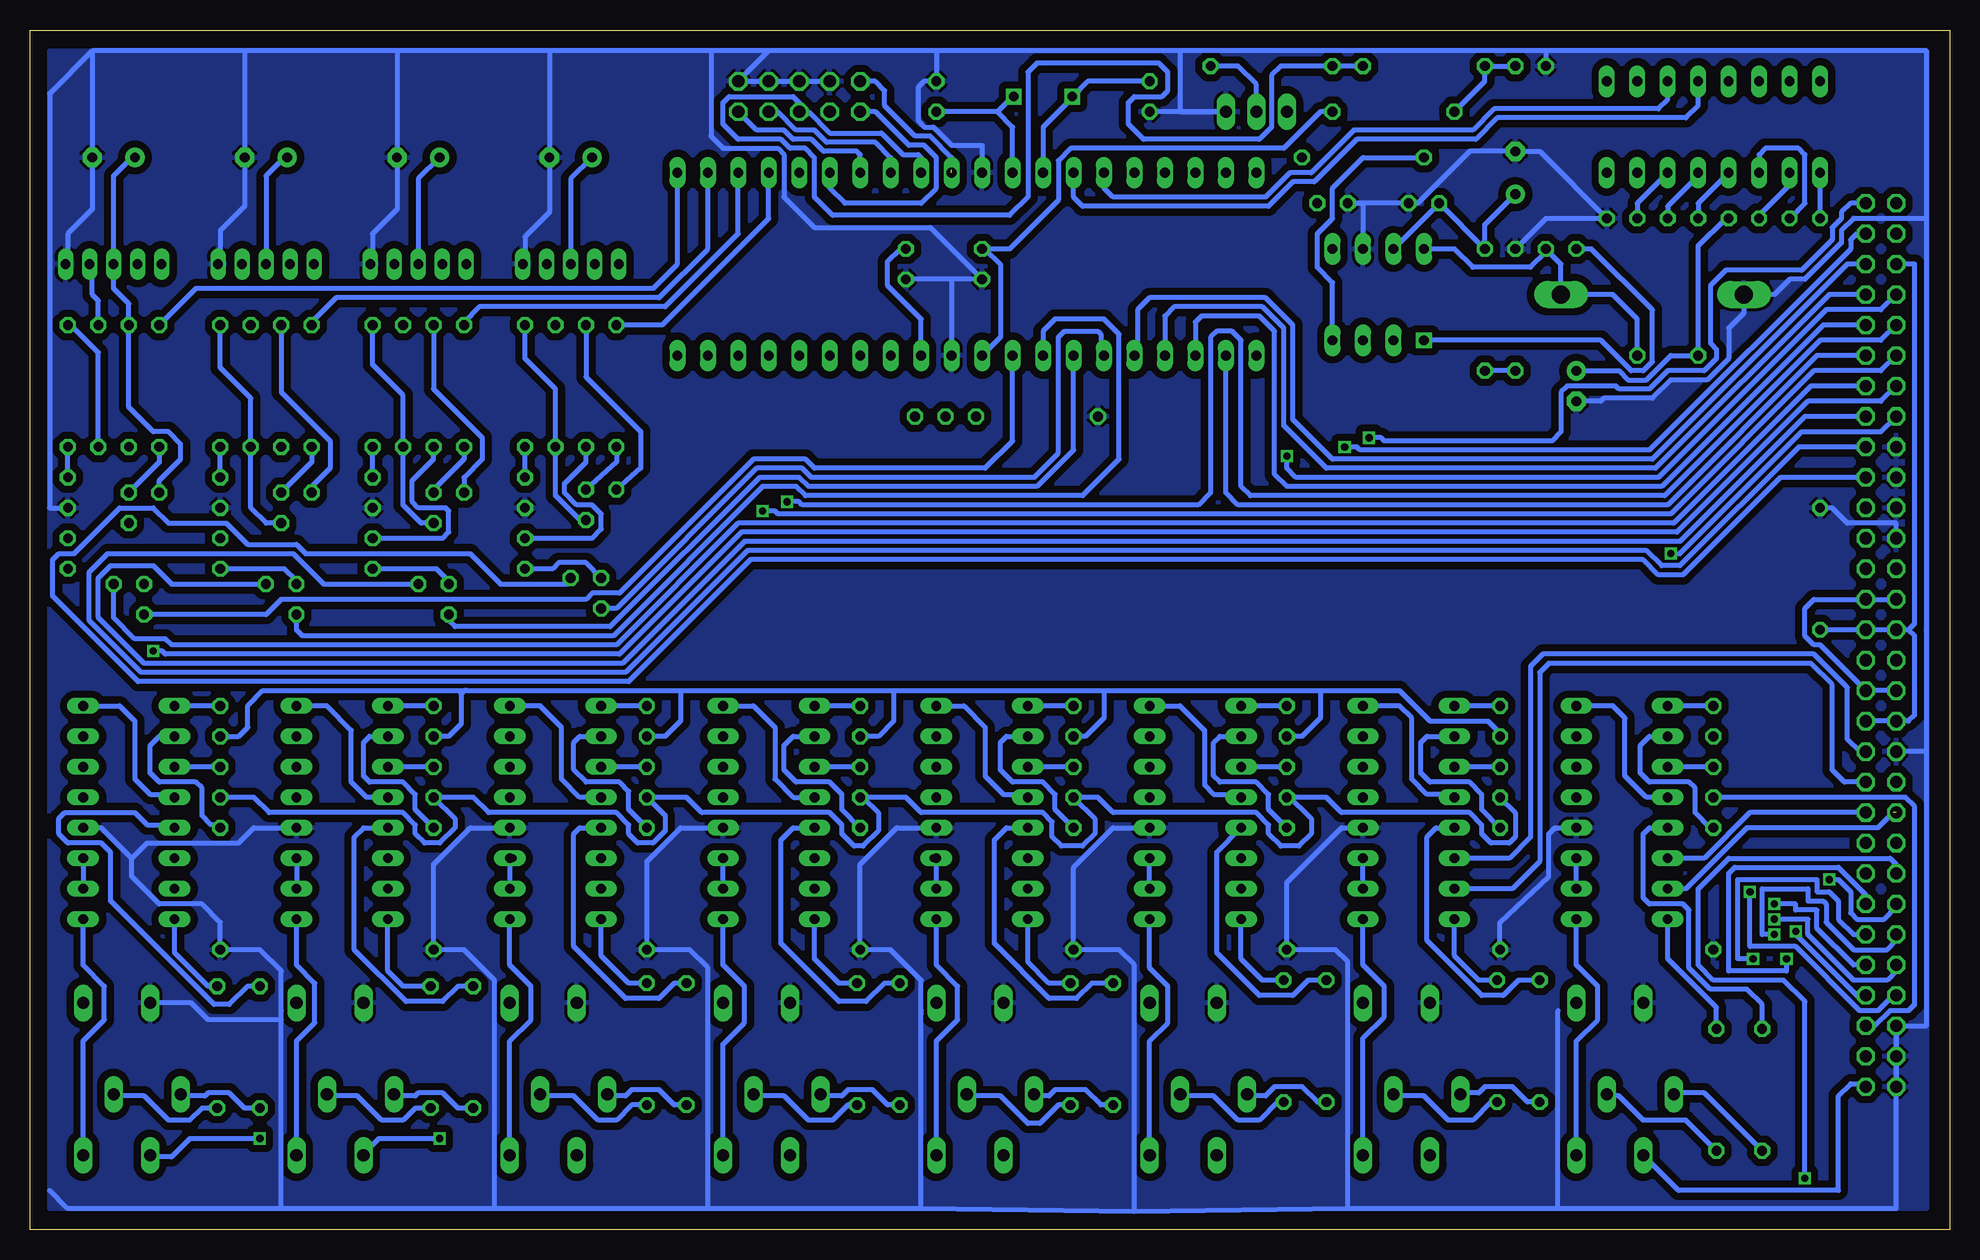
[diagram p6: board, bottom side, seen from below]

Size 160 x 100 mm. Coordinates in mm from the lower left corner, seen from the top.
Outline: 0,0 160,0 160,100 0,100 0,0
Copper layers (1*16): Top 0.035mm / dielectric 1.5mm / Bottom 0.035mm
Design rules "default": minimum track width 10mil, minimum drill 24mil, track to track 8mil, track to pad 8mil, pad to pad 8mil, via to via 8mil, smd to smd 8mil, copper to edge 40mil, drill to drill 8mil, minimum pad ring 10mil, minimum via ring 8mil, stop-mask expansion 4mil, vias tented up to drill 0mil, thermal gap 10mil

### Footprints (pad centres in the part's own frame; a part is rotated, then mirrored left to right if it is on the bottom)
C025-024X044 = drill 0.813 octagon: 1 -1.27,0; 2 1.27,0
E3,5-10 = drill 0.813 pad 1.6 round: + -1.778,0 | drill 0.813 pad 1.6 octagon: - 1.778,0
E2,5-5 = drill 0.813 pad 1.6 round: + -1.27,0 | drill 0.813 pad 1.6 octagon: - 1.27,0
C4111-15 = drill 1.499 long: A 7.62,0; C -7.62,0
DIL-8 = drill 0.813 square: P$1 -3.81,3.81 | drill 0.813 long: P$2 -3.81,1.27; P$3 -3.81,-1.27; P$4 -3.81,-3.81; P$5 3.81,-3.81; P$6 3.81,-1.27; P$7 3.81,1.27; P$8 3.81,3.81
0207/5V = drill 0.813 octagon: 1 -2.54,0; 2 2.54,0
LED3MM = drill 0.813 octagon: A -1.27,0; K 1.27,0
DIL40 = drill 0.813 long: 1 -24.13,-7.62; 2 -21.59,-7.62; 3 -19.05,-7.62; 4 -16.51,-7.62; 5 -13.97,-7.62; 6 -11.43,-7.62; 7 -8.89,-7.62; 8 -6.35,-7.62; 9 -3.81,-7.62; 10 -1.27,-7.62; 11 1.27,-7.62; 12 3.81,-7.62; 13 6.35,-7.62; 14 8.89,-7.62; 15 11.43,-7.62; 16 13.97,-7.62; 17 16.51,-7.62; 18 19.05,-7.62; 19 21.59,-7.62; 20 24.13,-7.62; 21 24.13,7.62; 22 21.59,7.62; 23 19.05,7.62; 24 16.51,7.62; 25 13.97,7.62; 26 11.43,7.62; 27 8.89,7.62; 28 6.35,7.62; 29 3.81,7.62; 30 1.27,7.62; 31 -1.27,7.62; 32 -3.81,7.62; 33 -6.35,7.62; 34 -8.89,7.62; 35 -11.43,7.62; 36 -13.97,7.62; 37 -16.51,7.62; 38 -19.05,7.62; 39 -21.59,7.62; 40 -24.13,7.62
SP19L = drill 1.016 long: A 5.715,-1.27; E -6.985,-1.27; S -1.905,1.27
0207/10 = drill 0.813 octagon: 1 -5.08,0; 2 5.08,0
0309/10 = drill 0.813 octagon: 1 -5.08,0; 2 5.08,0
MA10-2W = drill 1.016 octagon: 1 -11.43,-1.27; 2 -11.43,1.27; 3 -8.89,-1.27; 4 -8.89,1.27; 5 -6.35,-1.27; 6 -6.35,1.27; 7 -3.81,-1.27; 8 -3.81,1.27; 9 -1.27,-1.27; 10 -1.27,1.27; 11 1.27,-1.27; 12 1.27,1.27; 13 3.81,-1.27; 14 3.81,1.27; 15 6.35,-1.27; 16 6.35,1.27; 17 8.89,-1.27; 18 8.89,1.27; 19 11.43,-1.27; 20 11.43,1.27
MA05-2 = drill 1.016 octagon: 1 -5.08,-1.27; 2 -5.08,1.27; 3 -2.54,-1.27; 4 -2.54,1.27; 5 0,-1.27; 6 0,1.27; 7 2.54,-1.27; 8 2.54,1.27; 9 5.08,-1.27; 10 5.08,1.27
MA03-1 = drill 1.016 long: 1 -2.54,0; 2 0,0; 3 2.54,0
TO18 = drill 0.813 octagon: 1 -1.27,-1.27; 2 1.27,-1.27; 3 1.27,1.27
DIL-16 = drill 0.813 long: P$1 -3.81,8.89; P$2 -3.81,6.35; P$3 -3.81,3.81; P$4 -3.81,1.27; P$5 -3.81,-1.27; P$6 -3.81,-3.81; P$7 -3.81,-6.35; P$8 -3.81,-8.89; P$9 3.81,-8.89; P$10 3.81,-6.35; P$11 3.81,-3.81; P$12 3.81,-1.27; P$13 3.81,1.27; P$14 3.81,3.81; P$15 3.81,6.35; P$16 3.81,8.89
QUARZ16MHZ = drill 0.813 square: P$1 -2.44,0; P$2 2.44,0
TO-GEHÄUSE = drill 0.8 long: P$1 -4,0; P$2 -2,0; P$3 0,0; P$4 2,0; P$5 4,0

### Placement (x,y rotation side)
C1  43.81,85.56 0 top
C2  36.19,88.1 90 top
C3  31.11,70.32 270 top
C4  32.38,81.75 180 top
C5  34.92,96.99 180 top
C6  17.14,84.29 180 top
C7  27.3,84.29 180 top
C8  12.06,84.29 0 top
C9  22.22,84.29 180 top
C10  84.45,94.45 90 top
C11  66.67,94.45 90 top
C12  80.64,80.48 270 top
C13  86.99,80.48 270 top
C14  37.46,37.3 270 top
C15  37.46,42.38 270 top
C16  144.14,37.3 270 top
C17  144.14,42.38 270 top
C18  126.36,37.3 270 top
C19  126.36,42.38 270 top
C20  108.58,37.3 270 top
C21  108.58,42.38 270 top
C22  90.8,37.3 270 top
C23  90.8,42.38 270 top
C24  73.02,37.3 270 top
C25  73.02,42.38 270 top
C26  55.24,37.3 270 top
C27  55.24,42.38 270 top
C28  19.68,37.3 270 top
C29  19.68,42.38 270 top
C30  114.93,89.37 0 top
C31  127.63,89.37 0 top
C32  140.33,89.37 0 top
C33  153.03,89.37 0 top
D1  24.76,77.94 180 top
IC1  47.62,77.94 90 top
L1  23.49,72.86 180 top
LED1  51.43,85.56 180 top
LED2  118.74,61.43 270 top
LED3  118.74,56.35 270 top
LED4  131.44,61.43 270 top
LED5  131.44,56.35 270 top
LED6  144.14,61.43 270 top
LED7  144.14,56.35 270 top
LED8  156.84,61.43 270 top
LED9  156.84,56.35 270 top
LED10  84.96,67.78 180 top
MEGA16  81.91,80.48 180 top
OFFSET_AN1.1  42.03,13.17 90 top
OFFSET_AN1.2  148.71,13.17 90 top
OFFSET_AN1.3  24.25,13.17 90 top
OFFSET_AN1.4  130.93,13.17 90 top
OFFSET_AN1.5  113.15,13.17 90 top
OFFSET_AN1.6  95.37,13.17 90 top
OFFSET_AN1.7  77.59,13.17 90 top
OFFSET_AN1.8  59.81,13.17 90 top
R1  38.73,76.67 90 top
R2  36.19,76.67 270 top
R3  48.89,89.37 0 top
R4  46.35,93.18 180 top
R5  43.81,96.99 0 top
R6  56.51,96.99 180 top
R7  10.79,55.08 90 top
R8  34.16,15.71 270 top
R9  116.2,70.32 90 top
R10  118.74,70.32 90 top
R11  37.46,28.41 270 top
R12  140.84,15.2 270 top
R13  111.12,70.32 90 top
R14  128.9,70.32 90 top
R15  144.14,28.41 270 top
R16  123.06,15.2 270 top
R17  131.44,70.32 90 top
R18  123.82,70.32 90 top
R19  126.36,28.41 270 top
R20  105.28,15.46 270 top
R21  126.36,70.32 90 top
R22  141.6,70.32 90 top
R23  108.58,28.41 270 top
R24  87.5,15.46 270 top
R25  144.14,70.32 90 top
R26  136.52,70.32 90 top
R27  90.8,28.41 270 top
R28  69.72,15.46 270 top
R29  139.06,70.32 90 top
R30  154.3,70.32 90 top
R31  73.02,28.41 270 top
R32  51.94,15.71 270 top
R33  113.66,70.32 90 top
R34  156.84,70.32 90 top
R35  55.24,28.41 270 top
R36  15.62,11.65 270 top
R37  149.22,70.32 90 top
R38  151.76,70.32 90 top
R39  19.68,28.41 270 top
R40  76.07,67.78 0 top
RAN1.1  29.84,13.17 90 top
RAN1.2  19.43,11.65 90 top
RAN2.1  154.3,13.17 90 top
RAN2.2  144.39,15.2 90 top
RAN3.1  136.52,13.17 90 top
RAN3.2  126.61,15.2 90 top
RAN4.1  118.74,13.17 90 top
RAN4.2  108.58,15.46 90 top
RAN5.1  100.96,13.17 90 top
RAN5.2  91.05,15.46 90 top
RAN6.1  83.18,13.17 90 top
RAN6.2  73.27,15.46 90 top
RAN7.1  65.4,13.17 90 top
RAN7.2  55.49,15.71 90 top
RM1  47.62,13.17 90 top
RM2  37.71,15.71 90 top
SV1  5.71,48.73 90 top
SV2  5.71,74.13 90 top
SV3  5.71,23.33 90 top
SV4  95.88,94.45 0 top
SV5  57.78,93.18 180 top
T1  112.39,60.41 90 top
T2  125.09,60.16 90 top
T3  126.36,52.54 180 top
T4  137.79,60.16 90 top
T5  113.66,53.05 180 top
T6  139.06,52.54 180 top
T7  150.49,60.16 90 top
T8  151.76,52.54 180 top
U$1  19.68,91.91 90 top
U$2  75.56,94.45 0 top
U$3  45.08,34.76 0 top
U$4  151.76,34.76 0 top
U$5  133.98,34.76 0 top
U$6  116.2,34.76 0 top
U$7  98.42,34.76 0 top
U$8  80.64,34.76 0 top
U$9  62.86,34.76 0 top
U$10  27.3,34.76 0 top
U$11  114.93,80.48 180 top
U$12  127.63,80.48 180 top
U$13  140.33,80.48 180 top
U$14  153.03,80.48 180 top

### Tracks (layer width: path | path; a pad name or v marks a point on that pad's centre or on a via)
+5V  (via drill 0.6)  (1 unrouted)
  Top 0.406: R3.1 43.56,89.37 41.27,91.66 R4.2 | 51.43,75.65 51.94,76.16 81.15,76.16 83.18,78.19 MEGA16.10 | SV3.1 6.98,12.15 8,12.15 8.5,12.66 8.5,15.2 8,15.71 3.42,15.71 1.9,17.23 1.9,36.79 3.68,38.57 4.95,38.57 5.71,39.33 5.71,45.68 6.22,46.19 8.76,46.19 12.06,49.49 12.06,53.81 15.62,57.37 15.62,68.03 16.89,69.3 27.55,69.3 29.84,71.59 C3.+ 33.9,71.59 38.48,76.16 50.92,76.16 51.43,75.65 | 51.43,74.38 IC1.P$4 51.43,75.65 | OFFSET_AN1.3.E 26.16,6.18 27.55,7.58 29.59,7.58 30.35,8.34 31.62,8.34 32.38,7.58 43.3,7.58 | 43.3,7.58 47.62,7.58 48.38,8.34 49.4,8.34 50.16,7.58 61.08,7.58 | 61.08,7.58 65.15,7.58 65.91,8.34 67.43,8.34 68.19,7.58 78.86,7.58 | 78.86,7.58 82.93,7.58 83.69,8.34 85.21,8.34 85.97,7.58 96.64,7.58 | 96.64,7.58 100.71,7.58 101.47,8.34 102.99,8.34 103.75,7.58 114.42,7.58 | 114.42,7.58 118.49,7.58 119.25,8.34 120.77,8.34 121.53,7.58 v125.85,7.58 | OFFSET_AN1.2.E 149.98,6.06 | 114.42,7.58 OFFSET_AN1.5.E | 96.64,7.58 OFFSET_AN1.6.E | 78.86,7.58 OFFSET_AN1.7.E | 61.08,7.58 OFFSET_AN1.8.E | 43.3,7.58 OFFSET_AN1.1.E | v140.84,7.58 139.31,7.58 138.55,8.34 137.03,8.34 136.27,7.58 133.73,7.58 132.33,6.18 OFFSET_AN1.4.E
  Bottom 0.406: SV4.2 89.53,95.72 88.77,94.96 88.77,93.69 86.23,91.15 84.96,91.15 83.18,89.37 83.18,88.35 | C5.1 R5.1 38.73,95.72 R4.2 | C6.1 18.66,84.29 20.95,82 L1.2 23.24,72.86 25.27,70.83 26.79,70.83 27.55,71.59 C3.+ | R3.1 48.89,89.37 51.43,86.83 51.43,84.29 52.7,83.02 52.7,80.23 51.43,78.96 IC1.P$4 | OFFSET_AN1.3.E 22.6,3.26 9.27,3.26 9.27,11.14 8.25,12.15 6.98,12.15 SV3.1 | v140.84,7.58 146.68,7.58 148.2,6.06 149.98,6.06 OFFSET_AN1.2.E | OFFSET_AN1.4.E 132.2,6.31 130.93,7.58 v125.85,7.58
+12V
  Top 0.406: C33.+ 145.16,89.37 143.38,91.15 140.08,91.15 138.55,89.62 C32.+ 132.96,89.37 130.93,91.4 127.88,91.4 C31.+ 119.5,89.37 117.47,91.4 114.93,91.4 112.9,89.37 C30.+ 112.14,90.39 82.67,90.39 81.91,89.62 81.91,86.58 81.4,86.07 67.18,86.07 66.67,86.58 66.67,89.62 66.16,90.13 60.07,90.13 59.05,89.12 59.05,86.07 57.02,84.04 47.87,84.04 46.35,82.51 IC1.P$7 | U$11.P$3 114.93,76.67 R33.2 | U$12.P$3 127.63,76.67 R21.2 | U$13.P$3 140.33,76.67 R29.2 | T7.3 149.22,59.91 152.78,56.35 158.36,56.35 158.36,42.38 | SV3.3 5.71,13.17 5.71,3.01 6.98,1.74 158.36,1.74 158.36,42.38 | C29.2 20.19,41.11 21.46,39.84 35.94,39.84 37.21,41.11 C15.2 | C17.2 145.41,41.11 146.68,42.38 158.36,42.38
  Bottom 0.406: IC1.P$7 C1.1 R1.2 38.73,83.78 C2.+ | C33.+ 151.51,89.37 153.03,87.85 U$14.P$3 153.03,78.45 151.76,77.18 R38.2 152.01,75.15 151.76,74.89 151.76,68.54 149.73,66.51 148.46,66.51 147.44,65.49 147.44,64.22 149.22,62.45 T7.3 | C32.+ 138.55,89.62 140.33,87.85 U$13.P$3 | U$12.P$3 127.63,87.59 C31.+ | U$11.P$3 114.93,87.59 C30.+ | T2.3 123.82,62.7 122.3,64.22 122.3,66 126.36,70.07 R21.2 | T1.3 109.09,63.46 109.09,66.51 113.66,71.08 R33.2 | T4.3 136.52,61.94 135,63.46 135,65.75 139.06,69.81 R29.2 139.06,75.65 | 52.45,44.92 45.84,44.92 43.3,42.38 38.48,42.38 37.21,41.11 C15.2 | 70.48,44.92 52.45,44.92 | 88.01,44.92 70.48,44.92 | 105.79,44.92 88.01,44.92 | 123.57,44.92 105.79,44.92 | C27.2 53.97,41.11 52.45,42.63 52.45,44.92 | C25.2 72,41.11 70.48,42.63 70.48,44.92 | C23.2 89.28,41.11 88.01,42.38 88.01,44.92 | C21.2 107.06,41.11 105.79,42.38 105.79,44.92 | C19.2 125.09,41.11 124.07,42.13 124.07,44.67 123.82,44.92 123.57,44.92 | 123.57,44.92 140.58,44.92 141.85,43.65 141.85,41.87 142.62,41.11 C17.2
-12V
  Top 0.406: C28.2 19.93,36.03 21.2,34.76 36.19,34.76 C14.2
  Bottom 0.406: C16.2 141.35,36.03 140.08,34.76 128.9,34.76 127.88,33.74 127.88,32.98 127.12,32.22 125.85,32.22 124.58,33.49 124.58,34.25 C18.2 123.06,36.03 121.79,34.76 111.12,34.76 110.1,33.74 110.1,32.98 109.34,32.22 108.07,32.22 107.06,33.24 107.06,34.51 C20.2 105.28,36.03 104.01,34.76 93.34,34.76 92.32,33.74 92.32,32.98 91.31,31.97 90.55,31.97 89.28,33.24 89.28,34.76 90.55,36.03 C22.2 86.99,36.03 85.72,34.76 75.56,34.76 74.8,34 74.8,32.73 74.04,31.97 72.26,31.97 71.24,32.98 71.24,34.25 C24.2 70.99,36.03 69.72,34.76 57.78,34.76 56.76,33.74 56.76,32.98 55.75,31.97 54.22,31.97 53.21,32.98 53.21,34.25 55.24,36.28 C26.2 51.94,36.03 50.67,34.76 40,34.76 38.98,33.74 38.98,32.98 38.22,32.22 36.7,32.22 36.19,32.73 36.19,34.76 C14.2 | SV3.5 6.22,16.98 4.95,18.25 3.42,18.25 2.92,18.76 2.92,35.27 3.68,36.03 C28.2
AN1+
  Bottom 0.406: SV3.19 16.63,34.76 20.44,30.95 U$10.P$6
AN1-  (1 unrouted)
  Bottom 0.406: 4.69,34.76 5.96,33.49 16.89,33.49 21.97,28.41 U$10.P$7
AN1_10V  (via drill 0.6)
  Top 0.406: U$10.P$16 28.32,43.65 26.54,45.43 24.51,45.43 23.24,46.7 v23.24,56.35
  Bottom 0.406: U$10.P$16 28.06,43.65 27.05,42.63 27.05,37.81 25.27,36.03 U$10.P$4 | SV2.6 5.71,66.51 12.31,66.51 22.47,56.35 v23.24,56.35
AN2+
  Top 0.406: U$4.P$6 146.17,30.95 142.62,27.39 142.62,4.28 141.6,3.26 10.03,3.26 10.03,17.23 8.25,19.01 8.25,20.79 6.22,20.79 5.71,21.3 5.71,31.2 6.73,32.22 SV3.17
AN2-
  Top 0.406: U$4.P$7 147.19,28.41 145.92,27.14 145.92,3.52 144.9,2.5 9.27,2.5 9.27,16.73 7.74,18.25 3.42,18.25 2.92,18.76 2.92,31.71 3.42,32.22 SV3.18
AN2_10V  (via drill 0.6)
  Top 0.406: v149.73,48.22 151,48.22 U$4.P$16
  Bottom 0.406: U$4.P$16 152.52,43.65 151.25,42.38 151.25,37.55 149.98,36.28 147.7,36.28 U$4.P$4 | SV2.8 5.71,69.05 11.81,69.05 22.73,58.13 100.71,58.13 110.87,47.97 148.71,47.97 148.97,48.22 v149.73,48.22
AN3+
  Top 0.406: U$5.P$6 127.38,30.95 125.09,28.66 125.09,9.36 124.07,8.34 121.79,8.34 121.03,9.11 118.99,9.11 118.23,8.34 104.01,8.34 103.25,9.11 101.21,9.11 100.45,8.34 86.23,8.34 85.47,9.11 83.43,9.11 82.67,8.34 68.45,8.34 67.69,9.11 65.65,9.11 64.89,8.34 50.41,8.34 49.65,9.11 48.13,9.11 47.37,8.34 32.63,8.34 31.87,9.11 30.09,9.11 29.33,8.34 27.55,8.34 27.05,8.85 24.25,8.85 23.74,8.34 21.97,8.34 21.46,8.85 10.79,8.85 10.79,17.74 9.01,19.52 9.01,29.17 8.5,29.68 SV3.15
AN3-  (via drill 0.6)
  Top 0.406: U$5.P$7 128.9,28.41 127.88,27.39 127.88,5.04 126.87,4.03 14.09,4.03 13.84,4.28 v12.06,4.28
  Bottom 0.406: SV3.16 4.44,30.44 4.95,30.95 18.41,30.95 20.95,28.41 20.95,22.06 19.68,20.79 13.84,20.79 12.06,19.01 v12.06,4.28
AN3_10V  (via drill 0.6)
  Top 0.406: v98.93,59.91 98.93,58.89 110.61,47.46 112.64,47.46 115.44,44.67 115.44,32.22 117.98,29.68 125.09,29.68 127.88,32.47 127.88,35.27 128.65,36.03 U$5.P$4 130.42,36.03
  Bottom 0.406: U$5.P$16 135.25,43.65 133.22,41.62 133.22,37.3 131.95,36.03 U$5.P$4 129.92,36.03 | SV2.10 5.71,71.59 11.3,71.59 23.24,59.65 97.66,59.65 97.91,59.91 v98.93,59.91
AN4+  (via drill 0.6)
  Top 0.406: U$6.P$6 109.34,30.95 107.31,28.92 107.31,15.71 105.02,13.42 12.31,13.42 12.31,20.28 13.58,21.55 v13.58,22.57
  Bottom 0.406: SV3.13 6.98,27.9 9.27,30.19 17.9,30.19 18.41,29.68 18.41,21.55 13.58,21.55 v13.58,22.57
AN4-  (via drill 0.6)
  Top 0.406: U$6.P$7 110.87,28.41 110.1,27.65 110.1,10.12 109.09,9.11 104.26,9.11 103.5,9.87 100.96,9.87 100.2,9.11 86.48,9.11 85.72,9.87 83.18,9.87 82.42,9.11 68.7,9.11 67.94,9.87 65.4,9.87 64.64,9.11 50.67,9.11 49.91,9.87 47.87,9.87 47.11,9.11 32.89,9.11 32.13,9.87 29.84,9.87 29.08,9.11 27.81,9.11 27.3,9.61 24,9.61 23.49,9.11 22.22,9.11 21.71,9.61 11.55,9.61 11.55,18.25 10.03,19.77 v10.03,29.17
  Bottom 0.406: SV3.14 4.44,26.89 5.46,25.87 7.74,25.87 8.25,26.38 8.25,28.16 9.27,29.17 v10.03,29.17 9.77,29.17
AN4_10V  (via drill 0.6)
  Top 0.406: v96.9,60.67 96.9,59.91 110.1,46.7 112.39,46.7 114.68,44.41 114.68,36.54 114.17,36.03 U$6.P$4
  Bottom 0.406: U$6.P$16 117.47,43.65 115.69,41.87 115.69,37.55 114.17,36.03 U$6.P$4 | SV2.12 5.71,74.13 10.79,74.13 23.74,61.18 58.29,61.18 59.05,61.94 59.05,74.13 59.81,74.89 61.08,74.89 61.59,74.38 61.59,61.43 62.61,60.41 95.63,60.41 95.88,60.67 v96.9,60.67
AN5+  (via drill 0.6)
  Top 0.406: U$7.P$6 91.05,30.95 89.53,29.43 89.53,16.22 88.26,14.95 13.84,14.95 13.84,19.27 16.38,21.81 v16.38,22.57
  Bottom 0.406: SV3.11 8,24.6 9.27,25.87 9.27,27.39 10.03,28.16 11.04,28.16 11.04,29.17 17.65,29.17 17.65,22.57 v16.38,22.57
AN5-  (via drill 0.6)
  Top 0.406: U$7.P$7 93.09,28.41 92.32,27.65 92.32,15.46 91.05,14.19 13.08,14.19 13.08,19.77 14.6,21.3 v14.6,24.6
  Bottom 0.406: SV3.12 4.44,24.09 5.2,23.33 8,23.33 10.28,25.62 10.28,27.14 10.54,27.39 11.81,27.39 11.81,28.41 15.62,28.41 15.62,24.6 v14.6,24.6
AN5_10V  (via drill 0.6)
  Top 0.406: v55.24,64.48 85.47,64.48 102.23,47.71 U$7.P$16 102.48,43.4
  Bottom 0.406: U$7.P$16 99.69,43.65 97.91,41.87 97.91,37.55 96.39,36.03 U$7.P$4 | SV2.14 5.71,76.67 10.28,76.67 24.25,62.7 54.48,62.7 55.24,63.46 v55.24,64.48
AN6+  (via drill 0.6)
  Top 0.406: U$8.P$6 73.53,30.95 71.24,28.66 71.24,18 69.72,16.47 30.35,16.47 29.33,17.49 29.33,20.28 28.32,21.3 27.05,21.3 24.76,23.58 22.22,23.58 20.7,25.11 20.7,26.63 19.93,27.14 v14.6,27.14
  Bottom 0.406: SV3.9 8,22.06 11.04,25.11 11.04,26.63 12.82,26.63 12.82,27.14 v14.6,27.14
AN6-  (via drill 0.6)
  Top 0.406: U$8.P$7 75.56,28.41 74.54,27.39 74.54,16.98 73.27,15.71 30.09,15.71 28.57,17.23 28.57,19.77 27.81,20.54 26.79,20.54 24.51,22.82 21.97,22.82 18.92,25.87 v14.6,25.87
  Bottom 0.406: SV3.10 4.44,21.55 5.2,20.79 8,20.79 11.81,24.6 11.81,25.87 v14.6,25.87
AN6_10V  (via drill 0.6)
  Top 0.406: v50.41,65.24 52.19,63.46 85.47,63.46 101.21,47.71 101.21,45.94 100.2,44.92 88.51,44.92 87.24,43.65 U$8.P$16
  Bottom 0.406: U$8.P$16 82.16,43.65 80.39,41.87 80.39,37.81 78.86,36.28 77.34,36.28 77.08,36.03 U$8.P$4 | SV2.17 7.74,83.02 8.25,82.51 8.25,81.75 25.01,64.99 49.14,64.99 49.4,65.24 v50.41,65.24
AN7+  (via drill 0.6)
  Top 0.406: U$9.P$6 57.53,30.95 51.18,24.6 26.28,24.6 25.52,25.36 25.52,31.46 24.76,32.22 12.82,32.22 v12.82,24.85
  Bottom 0.406: SV3.7 7.74,19.52 12.82,24.6 v12.82,24.85
AN7-  (via drill 0.6)
  Top 0.406: U$9.P$7 57.78,28.41 51.43,22.06 27.55,22.06 25.27,24.35 22.47,24.35 21.46,25.36 21.46,27.14 20.44,28.16 v16.63,28.16
  Bottom 0.406: SV3.8 4.69,19.52 5.96,18.25 7.49,18.25 12.82,23.58 16.63,23.58 v16.63,28.16
AN7_10V  (via drill 0.6)
  Top 0.406: v48.38,66 48.38,65.24 51.18,62.45 85.47,62.45 100.45,47.46 100.45,46.44 99.94,45.94 88.26,45.94 87.24,44.92 70.48,44.92 69.21,43.65 U$9.P$16
  Bottom 0.406: U$9.P$16 64.13,43.65 62.1,41.62 62.1,37.05 61.34,36.28 59.05,36.28 U$9.P$4 | SV2.19 8.25,85.56 9.01,84.8 9.01,84.29 9.77,83.53 9.77,82.51 12.31,79.97 18.66,79.97 19.93,78.7 19.93,73.88 19.43,73.37 19.43,72.61 20.44,71.59 23.49,71.59 25.01,70.07 27.55,70.07 27.81,70.32 31.87,70.32 32.38,69.81 32.38,66.51 33.14,65.75 47.11,65.75 47.37,66 v48.38,66
DIG1IN
  Bottom 0.406: SV2.9 11.04,72.86 23.49,60.41 59.3,60.41 60.32,61.43 MEGA16.22
DIG2IN
  Bottom 0.406: SV2.11 10.54,75.4 24,61.94 55.24,61.94 56.26,62.95 56.26,74.89 57.53,76.16 62.35,76.16 62.86,75.65 MEGA16.23
DIG3IN
  Bottom 0.406: SV2.13 10.03,77.94 24.51,63.46 51.94,63.46 55.49,67.02 55.49,75.15 57.27,76.92 64.64,76.92 65.4,76.16 MEGA16.24
DIG4IN
  Bottom 0.406: SV2.15 8.5,80.48 24.76,64.22 51.43,64.22 54.73,67.53 54.73,75.4 57.02,77.69 66.67,77.69 67.69,76.67 67.69,73.37 67.94,73.11 MEGA16.25
FUSE_GND
  Top 0.406: LED2.K 119.5,60.16 120.26,60.92 120.26,76.16 118.74,77.69 118.74,79.97 118.99,80.23 118.93,80.29 U$11.P$1 | LED4.K 132.2,60.16 133.22,61.18 133.22,76.16 131.69,77.69 131.69,80.23 131.63,80.29 U$12.P$1 | LED6.K 145.16,60.16 145.92,60.92 145.92,76.92 144.39,78.45 144.39,80.48 U$13.P$1 | SV1.18 4.44,57.37 | SV1.18 SV1.20 SV2.2 SV2.4 SV1.18 | C5.2 33.65,92.42 C2.- | MEGA16.31 83.18,71.08 81.4,69.3 79.12,69.3 77.59,67.78 R40.1 | SV1.18 3.68,57.62 2.92,56.86 2.92,54.32 3.42,53.81 4.95,53.81 5.71,53.05 5.71,51.78 5.2,51.27 3.42,51.27 2.92,50.76 2.92,40.35 3.42,39.84 SV1.4 | OFFSET_AN1.3.A 24.12,18.88 R39.2
  Bottom 0.406: SV3.6 SV3.4 SV3.2 | SV3.6 4.44,1.74 32.63,1.74 | 139.06,1.74 156.84,1.74 158.36,3.26 | 121.28,1.74 139.06,1.74 | 103.5,1.74 121.28,1.74 | 85.72,1.74 103.5,1.74 | 67.94,1.49 85.72,1.74 | 50.16,1.74 67.94,1.49 | 32.63,1.74 50.16,1.74 | 154.81,98.26 158.36,94.7 158.36,60.16 LED8.K | 142.11,98.26 154.81,98.26 | 129.41,98.26 142.11,98.26 | 116.71,98.26 129.41,98.26 | 103.25,98.26 116.71,98.26 | 98.42,98.26 103.25,98.26 | 84.45,98.26 98.42,98.26 | 64.13,98.26 84.45,98.26 | 33.65,98.26 64.13,98.26 | 33.65,98.26 1.9,98.26 1.9,84.29 | 32.63,1.74 32.63,18.25 | 85.72,1.74 85.72,18 | 85.72,18 85.72,18.25 | 103.5,1.74 103.5,18.25 103.5,21.81 105.02,23.33 R23.2 108.58,30.7 105.79,33.49 U$7.P$12 101.98,33.49 | 121.28,1.74 121.28,18.25 121.28,20.79 123.82,23.33 R19.2 126.36,30.44 123.31,33.49 U$6.P$12 | 139.06,1.74 139.06,17.49 | 139.06,17.49 139.06,18.25 139.06,21.55 140.84,23.33 R15.2 144.14,25.62 145.66,27.14 149.22,27.14 151.51,29.43 151.51,30.95 | 154.81,98.26 C33.- 154.81,85.05 156.84,83.02 156.84,80.73 157.09,80.48 U$14.P$1 | 142.11,98.26 C32.- 142.11,85.31 144.14,83.27 144.14,80.73 144.39,80.48 U$13.P$1 | 129.41,98.26 C31.- 129.41,85.05 131.44,83.02 131.44,80.99 131.69,80.73 131.63,80.67 U$12.P$1 | 116.71,98.26 C30.- 116.71,84.8 118.74,82.77 118.74,80.73 118.99,80.48 U$11.P$1 | 98.42,98.26 SV4.10 SV4.8 SV4.6 SV4.4 | 84.45,98.26 C10.2 85.47,95.72 85.97,95.21 85.97,92.42 85.47,91.91 84.7,91.91 83.18,90.39 80.64,90.39 MEGA16.11 | C11.1 SV5.1 64.13,93.18 64.13,98.26 | 33.65,98.26 C5.2 | IC1.P$6 48.89,85.56 LED1.K C1.2 44.32,85.56 40,89.88 C2.- 34.16,89.88 C7.1 33.65,84.29 R2.1 | 1.9,39.84 1.9,84.29
  Bottom 0.406: 1.9,84.29 8,84.29 9.01,83.27 9.01,82.26 12.06,79.21 13.33,79.21 14.6,77.94 D1.A 17.14,76.42 18.41,75.15 18.41,72.61 20.19,70.83 23.24,70.83 24.76,69.3 28.82,69.3 29.08,69.05 C3.- | 87.24,79.21 C13.2 83.18,79.21 | 83.18,79.21 C12.2 84.96,83.53 94.61,83.53 97.15,86.07 97.15,89.62 97.66,90.13 102.23,90.13 103.25,91.15 103.25,98.26 | 83.18,79.21 MEGA16.31 | U$4.P$12 154.05,33.49 151.51,30.95 | U$5.P$12 141.35,33.49 142.62,32.22 150.24,32.22 151.51,30.95 | U$8.P$12 87.75,33.49 90.8,30.44 R27.2 88.26,23.33 85.72,20.79 85.72,18 | U$9.P$12 69.72,33.49 73.02,30.19 R31.2 69.21,23.33 67.94,22.06 67.94,1.49 | U$3.P$12 50.67,33.49 55.24,28.92 R35.2 51.18,23.33 50.16,22.31 50.16,1.74 | R11.2 37.46,25.62 33.4,29.43 33.4,32.98 32.89,33.49 U$10.P$12 | R7.2 9.77,60.16 8.5,58.89 4.44,58.89 SV1.18 4.44,57.37 | 1.9,39.84 SV1.4 | 1.9,39.84 1.9,16.98 SV3.6 | OFFSET_AN1.2.A 146.55,18.88 145.16,17.49 139.06,17.49
  pour Bottom (isolate 0.61): 1.9,98.26 1.9,1.74 158.36,1.74 158.36,98.26 156.33,98.26
  pour Top (isolate 0.61): 1.9,98.26 1.9,1.74 158.36,1.74 158.36,98.26 156.59,98.26
FUSE_TEST1
  Bottom 0.406: T5.3 111.12,51.78 99.44,63.46 95.63,63.46 94.86,62.7 76.32,62.7 74.29,64.73 74.29,74.38 73.78,74.89 70.99,74.89 70.73,74.64 70.73,73.11 MEGA16.26
FUSE_TEST2
  Bottom 0.406: T3.3 125.09,50.76 124.58,50.25 111.63,50.25 99.18,62.7 95.88,62.7 95.12,61.94 76.07,61.94 73.02,64.99 MEGA16.27
FUSE_TEST3
  Bottom 0.406: MEGA16.28 75.56,74.89 74.54,75.91 70.48,75.91 69.21,74.64 69.21,64.22 72.26,61.18 95.37,61.18 96.13,61.94 98.93,61.94 111.37,49.49 137.28,49.49 137.79,50 T6.3
FUSE_TEST4
  Bottom 0.406: T8.3 140.33,51.27 139.06,52.54 113.66,52.54 113.15,53.05 110.87,53.05 99.69,64.22 95.37,64.22 94.61,63.46 80.39,63.46 78.1,65.75 MEGA16.29
IGN1
  Bottom 0.406: R13.2 107.31,75.4 98.42,84.29 MEGA16.4
IGN1OUT
  Top 0.406: U$11.P$5 110.87,80.48 110.87,77.94 112.39,76.42 112.39,73.88 114.93,71.34 T5.1
  Bottom 0.406: SV2.1 14.09,62.7 22.22,54.57 24.25,54.57 25.52,55.84 99.94,55.84 110.1,45.68 151,45.68 158.11,52.79 158.11,55.84 157.6,56.35 156.33,56.35 152.52,60.16 149.73,60.16 148.46,58.89 143.63,58.89 141.85,57.11 137.79,57.11 137.03,56.35 123.31,56.35 120.77,53.81 115.18,53.81 114.93,54.06 T5.1
IGN2
  Bottom 0.406: MEGA16.3 100.96,83.02 107.06,76.92 122.55,76.92 123.82,75.65 R18.2
IGN2OUT
  Top 0.406: T3.1 127.63,71.59 125.09,74.13 125.09,76.42 123.57,77.94 123.57,80.23 123.63,80.29 U$12.P$5
  Bottom 0.406: SV2.3 12.57,65.24 22.47,55.33 24,55.33 25.27,56.6 100.2,56.6 110.36,46.44 150.74,46.44 155.06,50.76 155.06,54.83 153.54,56.35 138.04,56.35 135.5,53.81 T3.1
IGN3
  Bottom 0.406: MEGA16.2 103.5,81.75 107.56,77.69 134.49,77.69 136.52,75.65 R26.2
IGN3OUT
  Top 0.406: T6.1 140.33,61.94 137.79,64.48 137.79,77.43 136.52,78.7 136.52,80.23 136.33,80.42 U$13.P$5
  Bottom 0.406: SV2.5 12.06,67.78 22.47,57.37 100.45,57.37 110.61,47.21 150.49,47.21 154.3,51.02 154.3,54.32 153.28,55.33 149.73,55.33 148.2,53.81 T6.1
IGN4
  Bottom 0.406: MEGA16.1 106.04,80.48 108.07,78.45 146.17,78.45 R37.2
IGN4OUT
  Top 0.406: T8.1 153.03,54.83 147.7,60.16 147.7,77.18 148.97,78.45 148.97,80.48 U$14.P$5 149.03,80.42
  Bottom 0.406: SV2.7 11.55,70.32 22.98,58.89 100.96,58.89 111.12,48.73 148.2,48.73 148.71,49.24 151.25,49.24 153.03,51.02 T8.1
N$1
  Bottom 0.406: R2.2 R1.1
N$2
  Bottom 0.406: C4.2 29.84,81.75 24.76,76.67 24.76,72.35 25.52,71.59 26.54,71.59 29.08,74.13 IC1.P$1
N$3
  Bottom 0.406: IC1.P$8 41.27,81.75 39.75,80.23 34.92,80.23 33.65,81.5 C4.1 32.38,80.48 D1.C 28.06,77.94 26.03,75.91 L1.1
N$4
  Bottom 0.406: C6.2 15.87,84.54 13.33,87.08 U$1.P$2
N$5
  Top 0.406: R3.2 53.97,86.83 LED1.A
N$6
  Bottom 0.406: C7.2 26.03,85.56 U$1.P$6
N$7
  Bottom 0.406: U$1.P$5 20.7,88.1 23.49,85.31 C9.1
N$8
  Bottom 0.406: U$1.P$1 10.54,88.1 10.79,87.85 C8.1
N$9
  Bottom 0.406: C8.2 12.06,85.56 12.06,89.62 12.57,90.13 15.36,90.13 15.87,89.62 15.87,88.35 16.12,88.1 U$1.P$3
N$10
  Bottom 0.406: C9.2 20.95,85.56 U$1.P$4
N$11
  Top 0.406: SV1.17 11.3,57.62 12.06,58.38 12.06,90.13 13.33,91.4 16.38,91.4 18.41,93.43 U$1.P$13
N$12
  Top 0.406: SV1.19 7.49,60.16 8.5,61.18 8.5,90.39 11.04,92.93 14.85,92.93 15.87,93.94 U$1.P$14
N$13
  Bottom 0.406: MEGA16.14 73.02,86.07 72.26,85.31 56.76,85.31 54.73,87.34 52.95,87.34 49.4,90.89 39.49,90.89 37.71,92.67 21.97,92.67 20.95,93.69 U$1.P$12
N$14
  Bottom 0.406: MEGA16.15 70.48,86.83 69.72,86.07 57.02,86.07 54.99,88.1 53.21,88.1 49.65,91.66 39.75,91.66 37.97,93.43 24.25,93.43 23.49,94.2 U$1.P$11
N$15
  Bottom 0.406: MEGA16.13 75.56,91.91 73.02,94.45 U$2.P$1 71.85,95.72 C11.2
N$16
  Bottom 0.406: U$2.P$2 78.1,94.45 79.37,93.18 | 79.37,93.18 C10.1 | MEGA16.12 78.1,91.91 79.37,93.18
N$17
  Top 0.406: MEGA16.17 65.4,77.69 64.64,76.92 37.97,76.92 34.41,73.37 30.6,73.37 27.3,70.07 16.38,70.07 14.85,68.54 14.85,57.87 9.27,52.29 9.27,48.73 8,47.46 SV1.9
N$18
  Bottom 0.406: MEGA16.30 79.12,74.38 79.12,80.48 80.39,81.75 C12.1 78.35,81.75 74.29,85.81 74.29,89.12 73.27,90.13 55.49,90.13 52.45,93.18 R4.1
N$19
  Bottom 0.406: C13.1 87.5,81.75 88.51,80.73 88.51,78.7 85.72,75.91 MEGA16.32
N$20
  Bottom 0.406: MEGA16.9 85.72,89.37 85.97,89.62 87.24,89.62 89.02,91.4 93.34,91.4 95.12,93.18 SV4.5 95.88,93.94 96.39,94.45 101.72,94.45 102.23,93.94 102.23,92.16 100.96,90.89 97.4,90.89 96.64,90.13 95.37,90.13 94.61,89.37 94.61,86.07 93.09,84.54 78.35,84.54 76.83,86.07 76.83,96.48 76.07,97.24 65.91,97.24 65.15,96.48 65.15,94.96 65.65,94.45 67.94,94.45 68.45,93.94 68.45,92.16 67.18,90.89 57.53,90.89 56.51,91.91 56.51,96.23 55.75,96.99 R6.2 R5.2
N$21
  Top 0.406: SV2.20 4.44,96.48 6.22,98.26 66.92,98.26 67.94,97.24 MEGA16.16 67.94,87.85
N$22
  Bottom 0.406: R6.1 59.3,96.99 57.78,95.47 SV5.2
N$23
  Top 0.406: MEGA16.20 57.53,88.1 54.48,91.15 48.38,91.15 45.08,87.85 32.38,87.85 27.55,92.67 20.95,92.67 19.68,93.94 19.68,96.74 18.92,97.5 17.9,97.5 17.14,96.74 17.14,93.69 15.62,92.16 11.55,92.16 9.52,90.13 9.52,59.91 8.5,58.89 6.22,58.89 5.71,58.38 5.71,56.86 5.2,56.35 4.69,56.35 4.44,56.1 SV1.16
N$24
  Top 0.406: MEGA16.19 60.32,79.72 59.05,78.45 36.95,78.45 33.4,74.89 30.09,74.89 26.79,71.59 15.62,71.59 13.08,69.05 13.08,58.38 11.04,56.35 6.47,56.35 5.71,55.59 5.71,54.06 5.96,53.81 7.74,53.81 8.5,53.05 8.5,49.49 7.74,48.73 5.71,48.73 SV1.10
N$25
  Bottom 0.406: SV1.5 SV1.6 3.42,42.38 2.92,42.89 2.92,49.49 3.42,50 | R7.1 SV1.11 SV1.12 3.42,50 | 3.42,50 2.92,50.51 2.92,80.48 SV2.16
N$26
  Top 0.406: MEGA16.18 62.86,78.45 62.1,77.69 37.46,77.69 33.9,74.13 30.35,74.13 27.05,70.83 15.87,70.83 14.09,69.05 14.09,58.38 10.79,55.08 SV1.15
N$27
  Bottom 0.406: C14.1 U$3.P$3
N$28
  Bottom 0.406: U$3.P$1 41.27,43.4 41.02,43.65 C15.1
N$29
  Top 0.406: U$3.P$11 50.67,30.95 51.94,32.22 69.46,32.22 72,34.76 87.5,34.76 90.04,37.3 105.02,37.3 105.79,38.06 105.79,46.44 93.59,58.64 93.59,68.29 90.8,71.08 MEGA16.34
  Bottom 0.406: U$3.P$10 U$3.P$11
N$30
  Bottom 0.406: RM2.2 39.24,20.79 41.27,22.82 U$3.P$8
N$31
  Bottom 0.406: RM1.E 48.89,15.96 47.11,17.74 47.11,20.28 48.89,22.06 U$3.P$9
N$32
  Bottom 0.406: RM2.1 38.22,10.63 39.75,9.11 41.78,9.11 43.81,11.14 46.1,11.14 46.22,11.27 RM1.S
N$33
  Top 0.406: SV1.2 4.95,37.3 6.22,38.57 17.14,38.57 18.41,37.3 39.75,37.3 41.02,36.03 U$3.P$4
  Bottom 0.406: U$3.P$16 45.84,43.65 44.83,42.63 44.83,37.55 43.56,36.28 41.27,36.28 U$3.P$4
N$34
  Bottom 0.406: R11.1 38.98,35.01 38.98,36.28 40,37.3 43.3,37.3 44.06,38.06 44.06,40.6 43.56,41.11 U$3.P$2
N$35
  Bottom 0.406: C16.1 U$4.P$3
N$36
  Bottom 0.406: SV1.3 7.49,39.84 8.5,40.86 8.5,45.17 11.3,47.97 33.9,47.97 34.92,46.95 34.92,32.73 36.7,30.95 41.02,30.95 41.27,30.7 U$3.P$6
N$37
  Bottom 0.406: SV1.1 8.76,37.3 9.77,38.32 9.77,45.43 11.55,47.21 33.4,47.21 34.16,46.44 34.16,30.7 36.44,28.41 U$3.P$7
N$38
  Bottom 0.406: C17.1 U$4.P$1
N$39
  Top 0.406: U$4.P$11 153.54,30.95 153.54,36.79 153.03,37.3 142.87,37.3 141.6,38.57 141.6,45.43 137.03,50 111.88,50 106.04,55.84 MEGA16.40
  Bottom 0.406: U$4.P$11 U$4.P$10
N$40
  Bottom 0.406: RAN2.2.2 145.16,20.28 147.95,23.08 147.95,25.62 148.2,25.87 U$4.P$8
N$41
  Bottom 0.406: RAN2.1.E 155.57,15.71 153.79,17.49 153.79,20.28 155.57,22.06 155.57,25.36 155.82,25.62 U$4.P$9
N$42
  Bottom 0.406: RAN2.2.1 145.66,10.12 146.68,9.11 148.46,9.11 150.49,11.14 153.03,11.14 RAN2.1.S
N$43
  Bottom 0.406: U$4.P$2 149.22,41.11 149.98,40.35 149.98,38.06 149.22,37.3 146.17,37.3 145.66,36.79 145.66,34.51 144.9,33.74 144.39,33.74 R15.1
N$44
  Bottom 0.406: OFFSET_AN1.3.S 22.98,11.39 20.44,11.39 R36.2
N$45
  Top 0.406: U$11.P$2 116.93,76.13 R9.2
N$46
  Bottom 0.406: R8.2 35.17,10.63 36.44,11.9 38.73,11.9 39.24,11.39 40.51,11.39 40.64,11.27 OFFSET_AN1.1.S
N$47
  Bottom 0.406: 130.42,38.57 U$5.P$3 C18.1
N$48
  Bottom 0.406: C19.1 U$5.P$1
N$49
  Bottom 0.406: C26.1 U$9.P$3
N$50
  Bottom 0.406: U$5.P$8 130.17,21.55 128.9,20.28 RAN3.2.2
N$51
  Bottom 0.406: RAN3.1.E 137.79,15.71 136.27,17.23 136.27,20.54 137.79,22.06 U$5.P$9
N$52
  Bottom 0.406: RAN3.2.1 127.88,10.12 128.9,9.11 130.68,9.11 132.71,11.14 135,11.14 135.12,11.27 RAN3.1.S
N$53
  Bottom 0.406: R19.1 127.88,35.01 127.88,36.28 128.9,37.3 131.69,37.3 132.2,37.81 132.2,40.6 131.69,41.11 U$5.P$2
N$54
  Bottom 0.406: R12.2 142.11,10.12 143.38,11.39 145.16,11.39 145.41,11.14 147.19,11.14 147.31,11.27 OFFSET_AN1.2.S
N$55
  Bottom 0.406: R16.2 124.33,10.12 125.6,11.39 127.63,11.39 127.88,11.14 129.41,11.14 129.66,11.39 OFFSET_AN1.4.S
N$56
  Bottom 0.406: R20.2 106.29,10.38 107.56,11.65 109.85,11.65 110.36,11.14 111.63,11.14 111.75,11.27 OFFSET_AN1.5.S
N$57
  Bottom 0.406: C20.1 U$6.P$3
N$58
  Bottom 0.406: C21.1 U$6.P$1
N$59
  Bottom 0.406: C27.1 U$9.P$1
N$60
  Bottom 0.406: U$6.P$8 112.39,22.82 110.1,20.54 RAN4.2.2
N$61
  Bottom 0.406: RAN4.1.E 120.01,15.71 118.23,17.49 118.23,20.28 120.01,22.06 U$6.P$9
N$62
  Bottom 0.406: RAN4.2.1 109.85,10.38 111.12,9.11 112.64,9.11 114.68,11.14 117.22,11.14 117.47,11.39 RAN4.1.S
N$63
  Bottom 0.406: U$6.P$2 114.17,41.11 114.68,40.6 114.68,38.32 113.66,37.3 110.87,37.3 110.1,36.54 110.1,35.01 R23.1
N$64
  Bottom 0.406: R24.2 88.51,10.38 89.78,11.65 91.82,11.65 92.32,11.14 94.1,11.14 OFFSET_AN1.6.S
N$65
  Bottom 0.406: R28.2 70.73,10.38 72,11.65 74.54,11.65 75.05,11.14 76.32,11.14 OFFSET_AN1.7.S
N$66
  Top 0.406: R14.2 128.9,75.65 129.63,76.38 U$12.P$2
N$67
  Bottom 0.406: C22.1 U$7.P$3
N$68
  Bottom 0.406: C23.1 U$7.P$1
N$69
  Bottom 0.406: C28.1 U$10.P$3
N$70
  Bottom 0.406: U$7.P$8 94.61,22.57 92.58,20.54 RAN5.2.2
N$71
  Bottom 0.406: RAN5.1.E 102.23,15.46 100.45,17.23 100.45,20.28 102.23,22.06 U$7.P$9
N$72
  Bottom 0.406: RAN5.2.1 91.82,10.38 93.09,9.11 95.12,9.11 97.15,11.14 99.44,11.14 99.56,11.27 RAN5.1.S
N$73
  Bottom 0.406: R27.1 92.32,35.01 92.32,36.28 93.34,37.3 96.13,37.3 97.15,38.32 97.15,40.35 96.39,41.11 U$7.P$2
N$74
  Bottom 0.406: T1.1 113.91,58.89 116.2,61.18 R9.1 116.2,70.07 118.74,72.61 R10.2
N$75
  Bottom 0.406: R13.1 111.12,63.97 T1.2
N$76
  Bottom 0.406: LED3.K 116.45,55.08 115.95,55.59 113.66,55.59 T5.2
N$77
  Bottom 0.406: C24.1 U$8.P$3
N$78
  Bottom 0.406: C25.1 U$8.P$1
N$79
  Bottom 0.406: 23.74,43.65 U$10.P$1 C29.1
N$80
  Bottom 0.406: U$8.P$8 76.83,22.31 75.05,20.54 RAN6.2.2
N$81
  Bottom 0.406: RAN6.1.E 84.45,15.71 82.67,17.49 82.67,20.28 84.45,22.06 U$8.P$9
N$82
  Bottom 0.406: RAN6.2.1 74.29,10.38 75.81,8.85 76.83,8.85 79.12,11.14 82.16,11.14 82.04,11.27 RAN6.1.S
N$83
  Bottom 0.406: R31.1 74.54,35.01 74.54,36.28 75.56,37.3 78.1,37.3 79.12,38.32 79.12,40.6 78.61,41.11 U$8.P$2
N$84
  Bottom 0.406: T2.1 127.38,58.89 128.9,60.41 R14.1 128.9,69.56 131.44,72.1 R17.2
N$85
  Bottom 0.406: T2.2 126.61,61.43 123.82,64.22 R18.1
N$86
  Bottom 0.406: LED4.A R17.1
N$87
  Bottom 0.406: RAN7.2.2 57.27,20.79 59.05,22.57 U$9.P$8
N$88
  Top 0.406: U$5.P$11 135.25,30.95 133.98,32.22 133.98,45.68 130.68,48.98 111.63,48.98 103.5,57.11 103.5,72.61 103.25,72.86 MEGA16.39
  Bottom 0.406: U$5.P$11 U$5.P$10
N$89  (via drill 0.6)
  Top 0.406: v119.76,30.95 117.72,30.95 116.2,32.47 116.2,44.92 112.9,48.22 110.87,48.22 100.96,58.13 MEGA16.38 100.71,73.11
  Bottom 0.406: U$6.P$11 v119.76,30.95 120.01,30.7 U$6.P$10
N$90
  Top 0.406: U$7.P$11 108.33,30.95 110.36,32.98 110.36,45.43 95.88,59.91 95.88,68.54 98.42,71.08 MEGA16.37
  Bottom 0.406: 102.23,28.16 U$7.P$10 U$7.P$11
N$91  (via drill 0.6)
  Top 0.406: v84.7,30.95 90.04,30.95 91.31,32.22 104.77,32.22 107.31,34.76 107.31,47.21 95.12,59.65 95.12,70.57 95.88,71.34 MEGA16.36
  Bottom 0.406: U$8.P$11 v84.7,30.95 84.45,30.7 U$8.P$10
N$92
  Top 0.406: U$9.P$11 72.51,30.95 73.78,32.22 87.75,32.22 90.29,34.76 105.79,34.76 106.55,35.52 106.55,46.95 94.36,59.14 94.36,70.32 93.34,71.34 MEGA16.35
  Bottom 0.406: U$9.P$10 66.42,28.41 66.67,28.66 U$9.P$11
N$93
  Bottom 0.406: RAN7.1.E 66.67,15.71 65.15,17.23 65.15,20.28 66.67,21.81 U$9.P$9
N$94
  Bottom 0.406: RAN7.2.1 56,10.63 57.53,9.11 59.3,9.11 61.34,11.14 64.13,11.14 RAN7.1.S
N$95
  Bottom 0.406: R35.1 56.76,35.01 56.76,36.28 57.78,37.3 60.83,37.3 61.34,37.81 61.34,40.6 60.83,41.11 U$9.P$2
N$96
  Bottom 0.406: R21.1 126.36,64.22 128.14,62.45 128.14,60.67 127.63,60.16 125.34,60.16 125.09,59.91 125.09,58.13 125.6,57.62 LED5.A
N$97
  Bottom 0.406: T3.2 125.09,54.06 126.11,55.08 LED5.K
N$98
  Top 0.406: R22.2 141.6,75.65 142.33,76.38 U$13.P$2
N$99
  Top 0.406: U$10.P$11 37.97,30.95 39.24,32.22 39.24,34 40,34.76 68.7,34.76 71.24,37.3 87.75,37.3 90.29,39.84 104.01,39.84 105.02,40.86 105.02,45.94 92.83,58.13 92.83,66.51 88.26,71.08 MEGA16.33
  Bottom 0.406: U$10.P$10 U$10.P$11
N$100
  Bottom 0.406: RAN1.2.2 19.43,18.5 23.49,22.57 U$10.P$8
N$101
  Bottom 0.406: RAN1.1.E 31.11,15.71 29.33,17.49 29.33,20.28 31.11,22.06 31.11,25.36 31.36,25.62 U$10.P$9
N$102
  Bottom 0.406: RAN1.2.1 21.97,9.11 25.52,9.11 27.55,11.14 28.57,11.14 RAN1.1.S
N$103
  Bottom 0.406: R39.1 19.93,33.49 21.2,34.76 21.2,36.79 21.71,37.3 25.01,37.3 25.78,38.06 25.78,40.35 25.01,41.11 U$10.P$2
N$104
  Bottom 0.406: T4.1 140.33,58.89 141.6,60.16 R22.1 141.6,69.3 144.14,71.84 R25.2
N$105
  Bottom 0.406: R26.1 136.52,63.97 T4.2
N$106
  Bottom 0.406: LED6.A R25.1
N$107
  Bottom 0.406: SV4.7 97.66,93.18 96.13,91.66 94.61,91.66 93.59,90.64 89.53,90.64 88.26,89.37 MEGA16.8
N$108
  Bottom 0.406: SV4.1 89.53,93.18 86.74,90.39 85.47,90.39 84.45,89.37 84.45,86.83 85.72,85.56 92.07,85.56 93.34,86.83 MEGA16.6
N$109
  Bottom 0.406: SV4.9 99.44,91.66 97.15,91.66 96.39,90.89 94.86,90.89 93.85,89.88 91.05,89.88 90.8,89.62 MEGA16.7 90.8,87.85
N$110
  Top 0.406: R29.1 141.6,62.7 141.6,60.16 LED7.A
N$111
  Bottom 0.406: T6.2 137.79,54.06 138.81,55.08 LED7.K
N$112
  Bottom 0.406: R36.1 15.62,18.76 16.89,20.03 19.93,20.03 21.71,21.81 21.71,26.63 22.22,27.14 25.01,27.14 25.52,27.65 25.52,32.98 25.01,33.49 U$10.P$5 23.24,33.49
N$113
  Bottom 0.406: R8.1 35.94,20.79 37.21,19.52 38.98,19.52 43.56,24.09 43.56,32.73 42.79,33.49 U$3.P$5
N$114
  Bottom 0.406: R12.1 141.85,20.28 143.38,18.76 144.65,18.76 153.28,27.39 153.28,31.46 154.05,32.22 156.84,32.22 157.6,32.98 157.6,34.25 157.09,34.76 151.25,34.76 150.24,33.74 147.95,33.74 U$4.P$5
N$115
  Bottom 0.406: 129.92,33.49 U$5.P$5 132.2,33.49 132.96,32.73 132.96,23.33 128.65,19.01 125.6,19.01 124.33,20.28 R16.1
N$116
  Bottom 0.406: R20.1 106.29,20.54 107.56,19.27 110.36,19.27 114.68,23.58 114.68,32.98 114.17,33.49 U$6.P$5
N$117
  Bottom 0.406: R24.1 88.77,20.54 90.29,19.01 92.58,19.01 97.4,23.84 97.4,32.47 96.39,33.49 U$7.P$5
N$118
  Bottom 0.406: R28.1 71.5,20.54 72.77,19.27 75.05,19.27 79.62,23.84 79.62,32.47 78.61,33.49 U$8.P$5
N$119
  Bottom 0.406: R32.1 53.46,20.79 54.73,19.52 57.53,19.52 61.08,23.08 61.08,31.46 U$9.P$5
N$120
  Bottom 0.406: LED2.A R10.1
N$121
  Bottom 0.406: R33.1 113.66,63.97 115.44,62.19 115.44,61.43 114.42,60.41 113.15,60.41 112.39,59.65 112.39,58.38 113.15,57.62 LED3.A
N$122
  Bottom 0.406: R30.2 154.3,77.43 154.81,77.94 154.81,79.97 155.06,80.23 155.03,80.26 U$14.P$2
N$123
  Top 0.406: R30.1 154.3,66 153.54,66.76 150.74,66.76 150.49,66.51 150.49,64.22 151.51,63.21 152.52,63.21 153.28,62.45 153.28,60.16 152.01,58.89 T7.1
  Bottom 0.406: R34.2 156.59,75.4 154.3,73.11 R30.1
N$124
  Bottom 0.406: R37.1 149.22,63.97 T7.2
N$125
  Bottom 0.406: LED8.A R34.1
N$126
  Top 0.406: R38.1 154.3,62.7 154.3,60.16 LED9.A
N$127
  Top 0.406: LED9.K 156.84,53.56 155.57,52.29 152.01,52.29 T8.2
N$128
  Top 0.406: LED10.A 86.99,68.54 86.99,74.64 95.88,83.53 MEGA16.5
N$129
  Top 0.406: R40.2 LED10.K
N$130
  Bottom 0.406: R32.2 52.7,10.63 53.97,11.9 56.26,11.9 57.02,11.14 58.29,11.14 58.41,11.27 OFFSET_AN1.8.S
V+
  Top 0.406: SV2.18 2.41,83.02 1.9,82.51 1.9,53.3 2.66,52.54 4.19,52.54 4.44,52.29 SV1.14
  Bottom 0.406: SV1.8 SV1.7 10.79,48.73 11.3,48.73 12.06,49.49 12.06,51.78 11.3,52.54 6.73,52.54 | 6.73,52.54 SV1.14 | 6.73,52.54 SV1.13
